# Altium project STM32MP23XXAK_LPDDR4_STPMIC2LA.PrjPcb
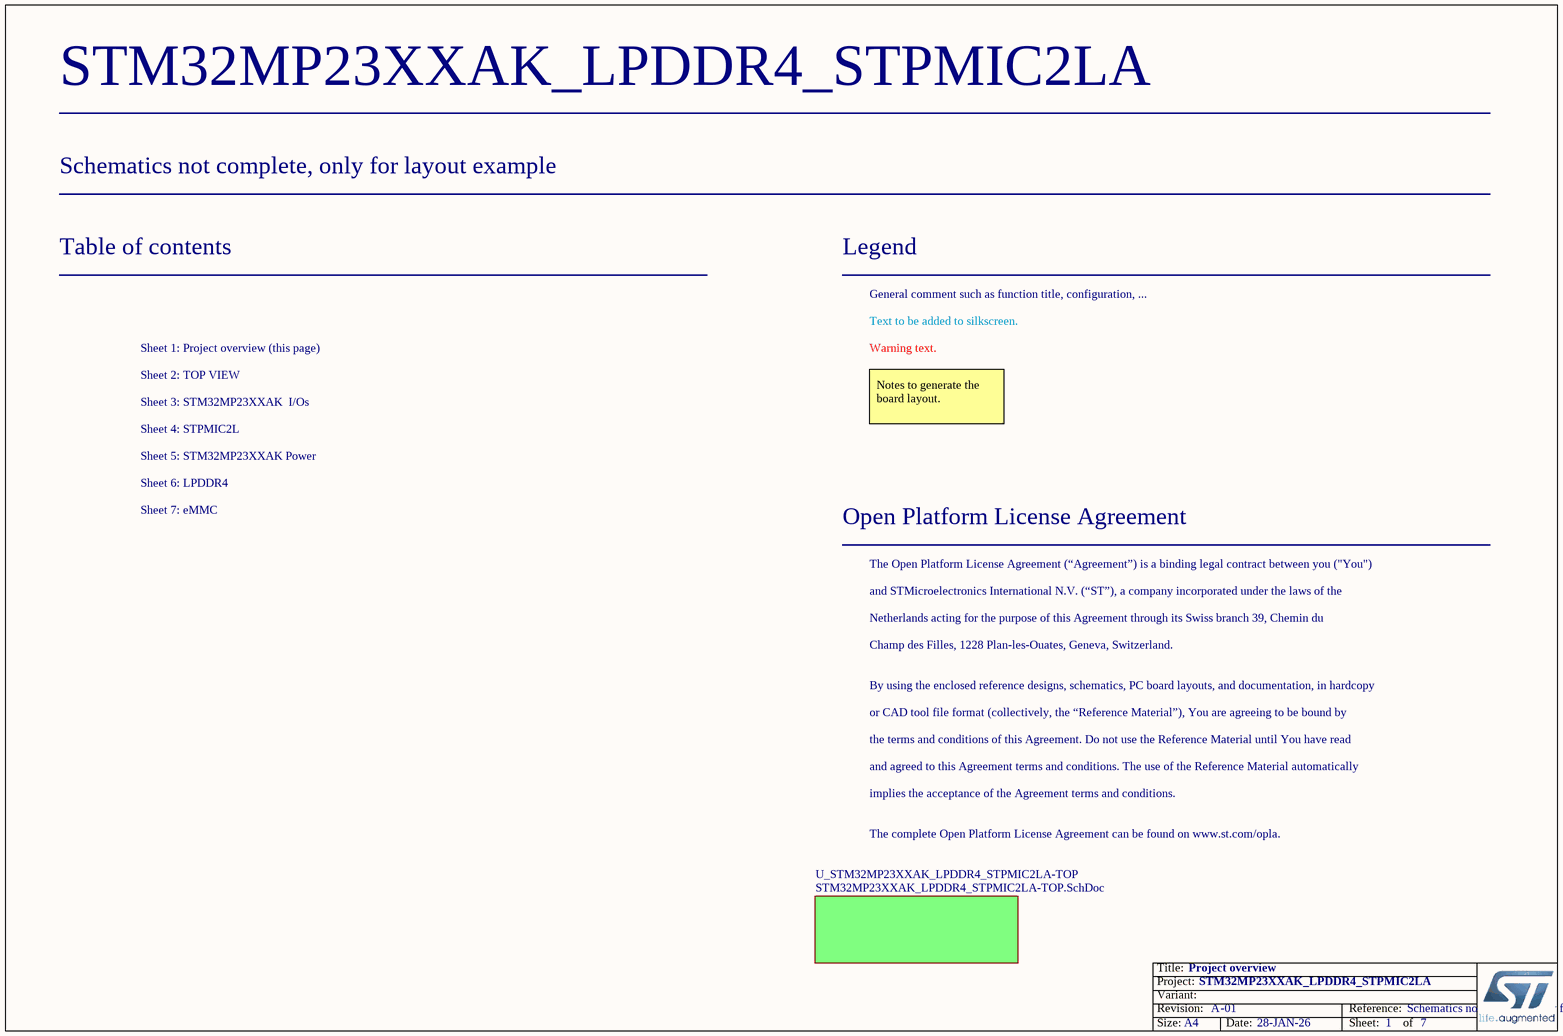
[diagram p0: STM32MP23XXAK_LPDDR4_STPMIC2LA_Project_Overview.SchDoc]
Board_Reference: Schematics not complete, only for layout example; Board_PCB_Revision: A; Board_Name: STM32MP23XXAK_LPDDR4_STPMIC2LA; Board_Document_Date: 28-JAN-26; Board_Assembly_Revision: 01
7 sheets, 156 parts. Net scope: flat (ports and power ports of the same name join across sheets).
Board file: STM32MP23XXAK_LPDDR4_STPMIC2L.PcbDoc
Sheets:
  STM32MP23XXAK_LPDDR4_STPMIC2LA_Project_Overview.SchDoc
    U_STM32MP23XXAK_LPDDR4_STPMIC2LA-TOP = STM32MP23XXAK_LPDDR4_STPMIC2LA-TOP.SchDoc
      U_STM32MP23XXAK I_Os = STM32MP23XXAK I_Os.SchDoc
      U_PMIC = STPMIC2L.SchDoc
      U_STM32MP23XXAK Power = STM32MP23XXAK Power.SchDoc
      U_LPDDR4 = LPDDR4.SchDoc
      U_eMMC = eMMC.SchDoc

## Sheet STM32MP23XXAK_LPDDR4_STPMIC2LA_Project_Overview.SchDoc: Project overview
size A4; Date: Not used; ApprovedBy: Not used; CheckedBy: Not used; Author: Not used; CompanyName: STMicroelectronics; DrawnBy: Not used; Engineer: Not used; Organization: Not used; Address1: Not used; Address2: Not used; Address3: Not used; Address4: Not used; DocumentNumber: Not used; Revision: Not used; SheetNumber: 1; SheetTotal: 7

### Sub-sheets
U_STM32MP23XXAK_LPDDR4_STPMIC2LA-TOP = STM32MP23XXAK_LPDDR4_STPMIC2LA-TOP.SchDoc: no entries

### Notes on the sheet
- Table of contents
- Legend
- General comment such as function title, configuration, ...
- Sheet 1: Project overview (this page)
- Sheet 2: TOP VIEW
- Text to be added to silkscreen.
- Warning text.
- Sheet 3: STM32MP23XXAK  I/Os
- Sheet 4: STPMIC2L
- Notes to generate the board layout.
- Sheet 5: STM32MP23XXAK Power
- Sheet 7: eMMC
- Sheet 6: LPDDR4
- Open Platform License Agreement
- The Open Platform License Agreement (“Agreement”) is a binding legal contract between you ("You")
- and STMicroelectronics International N.V. (“ST”), a company incorporated under the laws of the
- Netherlands acting for the purpose of this Agreement through its Swiss branch 39, Chemin du
- Champ des Filles, 1228 Plan-les-Ouates, Geneva, Switzerland.
- By using the enclosed reference designs, schematics, PC board layouts, and documentation, in hardcopy
- or CAD tool file format (collectively, the “Reference Material”), You are agreeing to be bound by
- the terms and conditions of this Agreement. Do not use the Reference Material until You have read
- and agreed to this Agreement terms and conditions. The use of the Reference Material automatically
- implies the acceptance of the Agreement terms and conditions.
- The complete Open Platform License Agreement can be found on www.st.com/opla.

## Sheet STM32MP23XXAK_LPDDR4_STPMIC2LA-TOP.SchDoc: STM32MP25XXAK-TOP
size A3; Date: Not used; ApprovedBy: Not used; CheckedBy: Not used; Author: Not used; CompanyName: STMicroelectronics; DrawnBy: Not used; Engineer: Not used; Organization: Not used; Address1: Not used; Address2: Not used; Address3: Not used; Address4: Not used; DocumentNumber: Not used; Revision: Not used; SheetNumber: 2; SheetTotal: 7
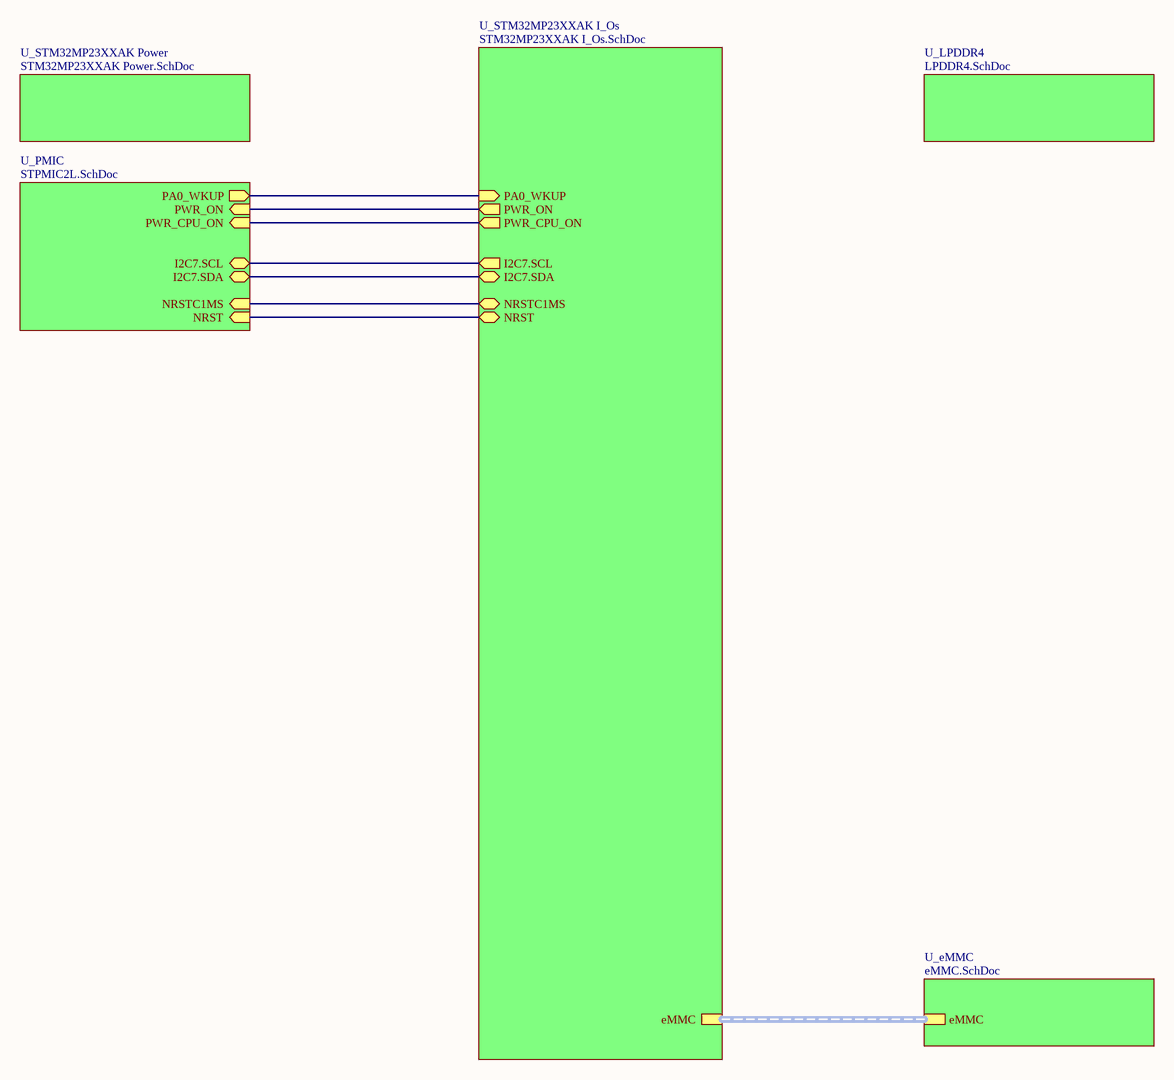
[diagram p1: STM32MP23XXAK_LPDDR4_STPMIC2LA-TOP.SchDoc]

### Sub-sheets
U_eMMC = eMMC.SchDoc: eMMC (harness eMMC)
U_LPDDR4 = LPDDR4.SchDoc: no entries
U_PMIC = STPMIC2L.SchDoc: NRST (in), I2C7.SCL (bidir), PWR_ON (in), PWR_CPU_ON (in), NRSTC1MS (in), I2C7.SDA (bidir), PA0_WKUP (out)
U_STM32MP23XXAK I_Os = STM32MP23XXAK I_Os.SchDoc: NRST (bidir), PWR_ON (out), NRSTC1MS (bidir), I2C7.SDA (bidir), I2C7.SCL (out), PWR_CPU_ON (out), PA0_WKUP (in), eMMC (harness eMMC)
U_STM32MP23XXAK Power = STM32MP23XXAK Power.SchDoc: no entries

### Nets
(unnamed): sheet U_STM32MP23XXAK I_Os/NRST, sheet U_PMIC/NRST
(unnamed): sheet U_STM32MP23XXAK I_Os/PWR_ON, sheet U_PMIC/PWR_ON  [a separate net that carries the same name]
(unnamed): sheet U_STM32MP23XXAK I_Os/NRSTC1MS, sheet U_PMIC/NRSTC1MS  [a separate net that carries the same name]
(unnamed): sheet U_STM32MP23XXAK I_Os/I2C7.SDA, sheet U_PMIC/I2C7.SDA  [a separate net that carries the same name]
(unnamed): sheet U_STM32MP23XXAK I_Os/I2C7.SCL, sheet U_PMIC/I2C7.SCL  [a separate net that carries the same name]
(unnamed): sheet U_STM32MP23XXAK I_Os/PWR_CPU_ON, sheet U_PMIC/PWR_CPU_ON  [a separate net that carries the same name]
(unnamed): sheet U_STM32MP23XXAK I_Os/PA0_WKUP, sheet U_PMIC/PA0_WKUP  [a separate net that carries the same name]

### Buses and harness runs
harness sheet U_eMMC/eMMC = sheet U_STM32MP23XXAK I_Os/eMMC

## Sheet STM32MP23XXAK I_Os.SchDoc: STM32MP25XXAK  I/Os
size A3; Date: Not used; ApprovedBy: Not used; CheckedBy: Not used; Author: Not used; CompanyName: STMicroelectronics; DrawnBy: Not used; Engineer: Not used; Organization: Not used; Address1: Not used; Address2: Not used; Address3: Not used; Address4: Not used; DocumentNumber: Not used; Revision: Not used; SheetNumber: 3; SheetTotal: 7
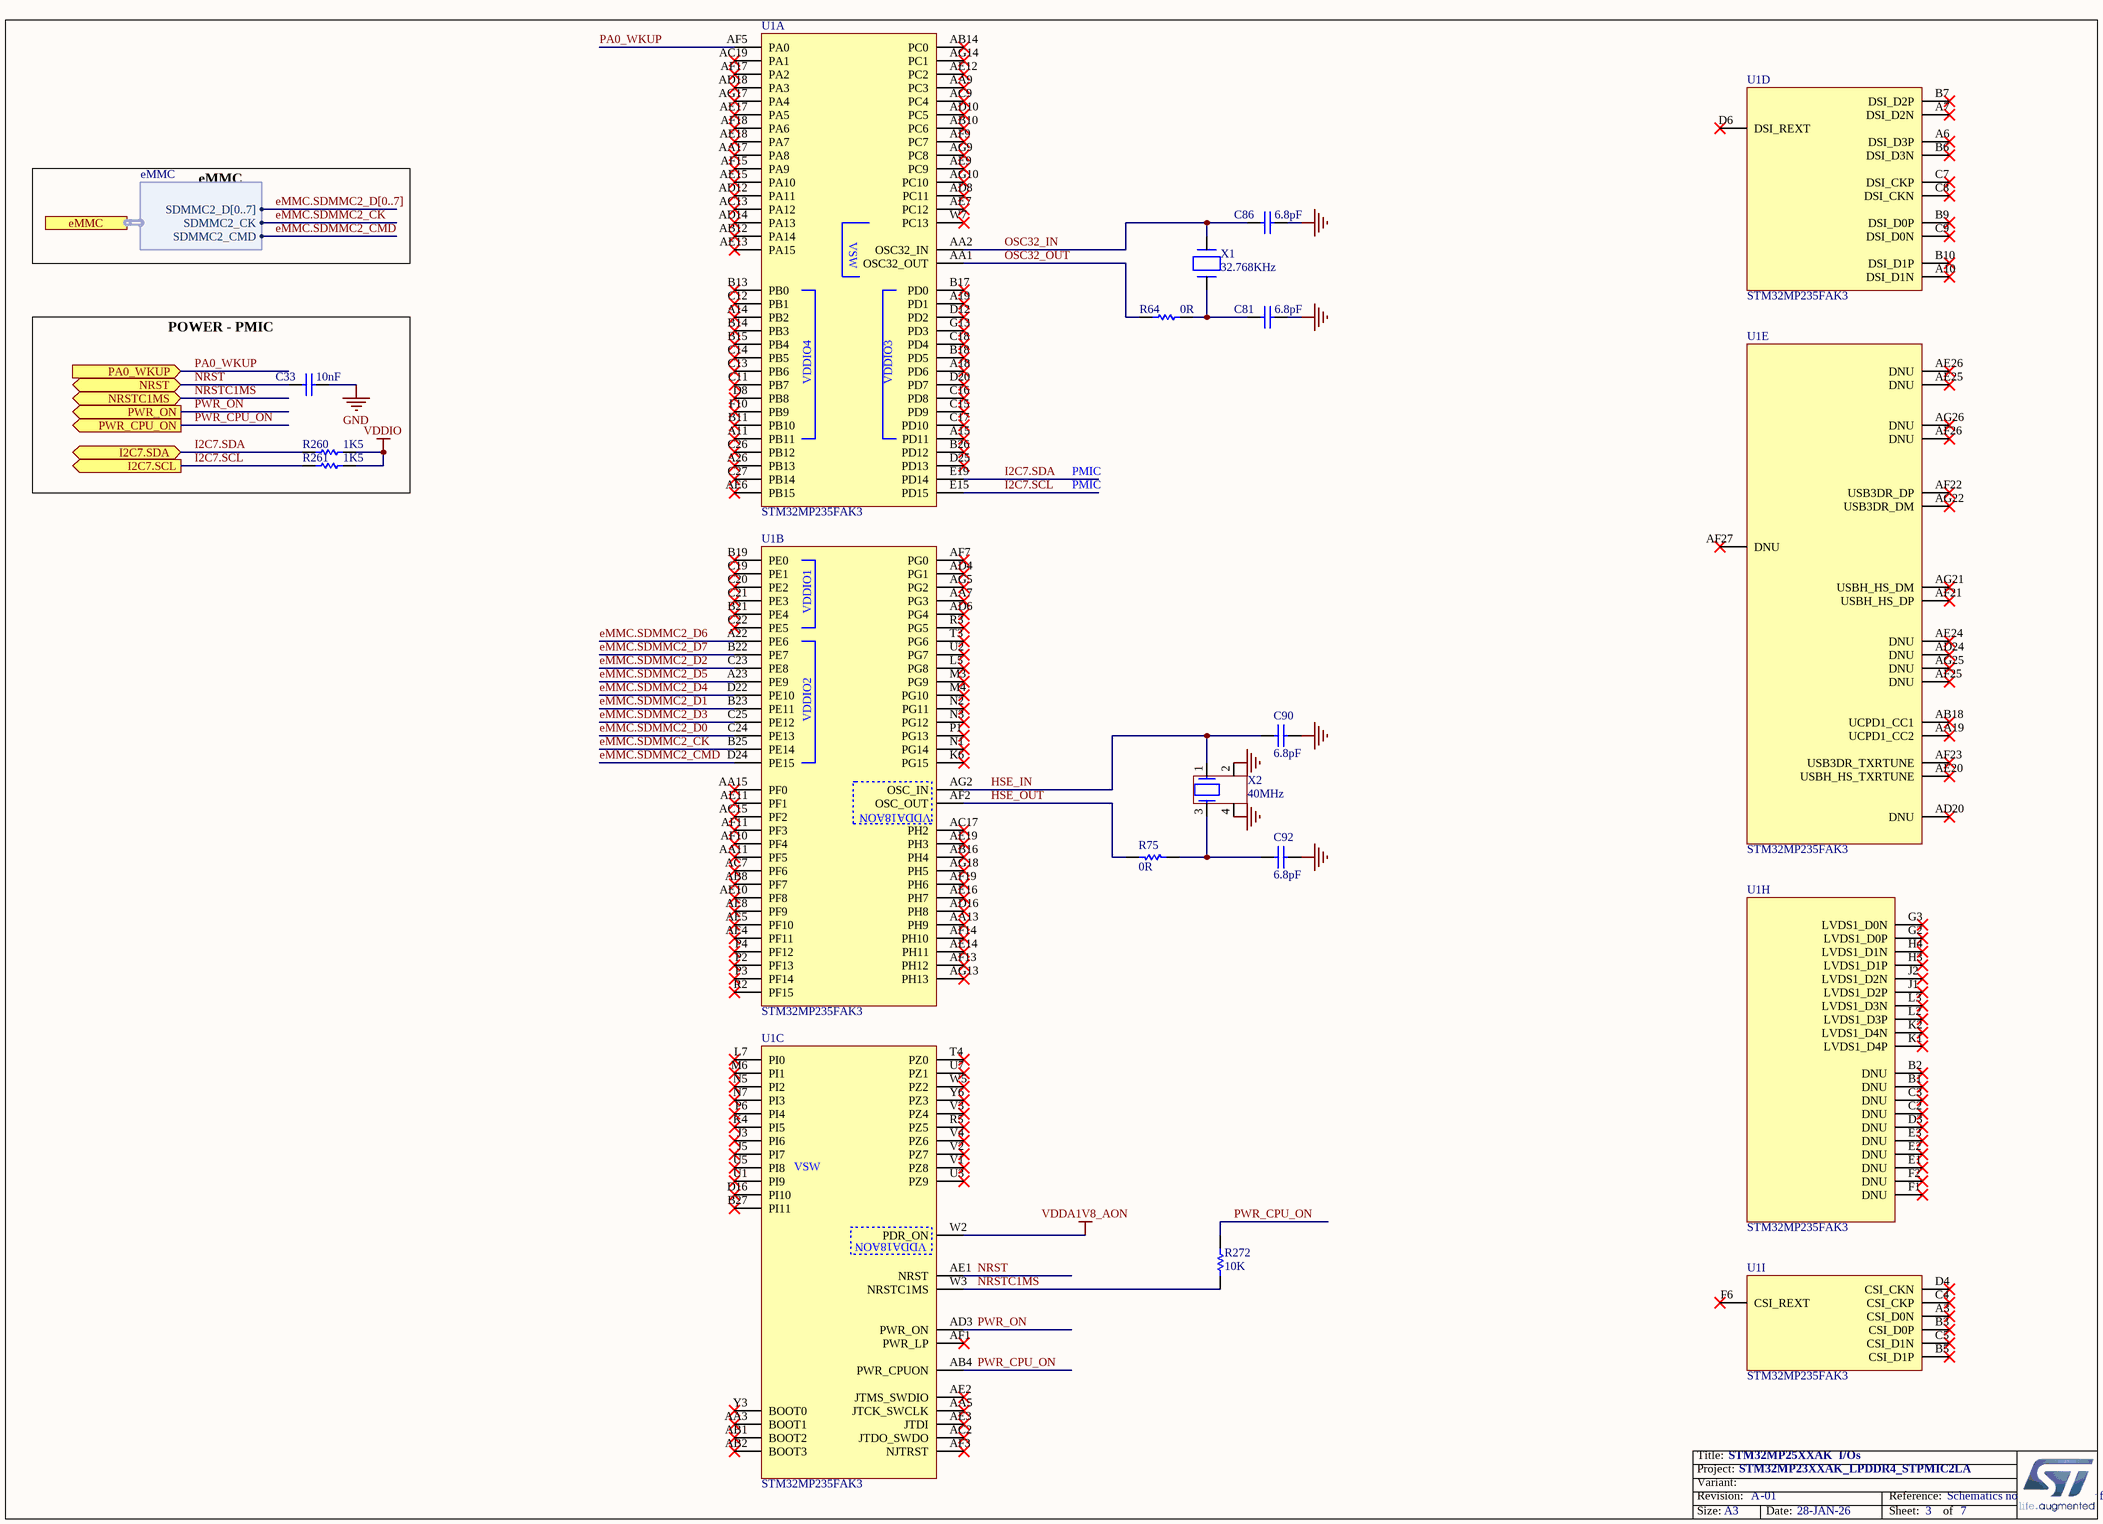
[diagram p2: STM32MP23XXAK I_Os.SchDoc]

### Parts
C33  value 10nF  [C0402]  (hidden comment: Capacitor)
C81  value 6.8pF  [C0402]  (hidden comment: Capacitor)
C86  value 6.8pF  [C0402]  (hidden comment: Capacitor)
C90  value 6.8pF  [C0402]  (hidden comment: Capacitor)
C92  value 6.8pF  [C0402]  (hidden comment: Capacitor)
R64  value 0R  [R0402]  (hidden comment: Resistor)
R75  value 0R  [R0402]  (hidden comment: Resistor)
R260  value 1K5  [R0402]  (hidden comment: Resistor)
R261  value 1K5  [R0402]  (hidden comment: Resistor)
R272  value 10K  [R0402]  (hidden comment: Resistor)
U1  value STM32MP235FAK3  [ICC_VFBGA424_14X14_P050_H1P0_CODE-B0MP]  (hidden comment: IC_STM32MP235FAK3)  (parts A,B,C,D,E,H,I of 9)
X1  value 32.768KHz  [CRY_NX2012SA_2P]  (hidden comment: XTAL_2_PINS)
X2  value 40MHz  [CRY_NX1612SA_4P]  (hidden comment: XTAL_4_PINS)

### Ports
eMMC (harness eMMC), I2C7.SCL (out), I2C7.SDA (bidir), NRST (bidir), NRSTC1MS (bidir), PA0_WKUP (in), PWR_CPU_ON (out), PWR_ON (out)

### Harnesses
eMMC: SDMMC2_CK, SDMMC2_CMD, SDMMC2_D[0..7]

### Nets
GND: C33.1 C81.2 C86.2 C90.1 C92.2 X2.2 X2.4
VDDA1V8_AON: U1.W2(PDR_ON)
VDDIO: R260.2 R261.2
eMMC.SDMMC2_CK: U1.B25(PE14) ; port eMMC.SDMMC2_CK
eMMC.SDMMC2_CMD: U1.D24(PE15) ; port eMMC.SDMMC2_CMD
eMMC.SDMMC2_D0: U1.C24(PE13)
eMMC.SDMMC2_D1: U1.B23(PE11)
eMMC.SDMMC2_D2: U1.C23(PE8)
eMMC.SDMMC2_D3: U1.C25(PE12)
eMMC.SDMMC2_D4: U1.D22(PE10)
eMMC.SDMMC2_D5: U1.A23(PE9)
eMMC.SDMMC2_D6: U1.A22(PE6)
eMMC.SDMMC2_D7: U1.B22(PE7)
HSE_IN: C90.2 U1.AG2(OSC_IN) X2.1
HSE_OUT: R75.2 U1.AF2(OSC_OUT)
I2C7.SCL: R261.1 U1.E15(PD15) ; port I2C7.SCL
I2C7.SDA: R260.1 U1.E19(PD14) ; port I2C7.SDA
NRST: C33.2 U1.AE1(NRST) ; port NRST
NRSTC1MS: R272.1 U1.W3(NRSTC1MS) ; port NRSTC1MS
OSC32_IN: C86.1 U1.AA2(OSC32_IN) X1.2(X2)
OSC32_OUT: R64.1 U1.AA1(OSC32_OUT)
PA0_WKUP: U1.AF5(PA0) ; port PA0_WKUP
PWR_CPU_ON: R272.2 U1.AB4(PWR_CPUON) ; port PWR_CPU_ON
PWR_ON: U1.AD3(PWR_ON) ; port PWR_ON
NetC81_1: C81.1 R64.2 X1.1(X1)
NetC92_1: C92.1 R75.1 X2.3

Not connected (* = marked no-connect by the designer): U1 A3(CSI_D0N)* A6(DSI_D3P)* A7(DSI_D2N)* A10(DSI_D1N)* A11(PB11)* A14(PB2)* A15(PD11)* A18(PD6)* A19(PD1)* A26(PB13)* AA3(BOOT1)* AA5(JTCK_SWCLK)* AA7(PG3)* AA9(PC3)* AA11(PF5)* AA13(PH9)* AA15(PF0)* AA17(PA8)* AA19(UCPD1_CC2)* AB1(BOOT2)* AB2(BOOT3)* AB8(PF7)* AB10(PC6)* AB12(PA14)* AB14(PC0)* AB16(PH4)* AB18(UCPD1_CC1)* AC2(JTDO_SWDO)* AC7(PF6)* AC9(PC4)* AC13(PA12)* AC15(PF2)* AC17(PH2)* AC19(PA1)* AD4(PG1)* AD6(PG4)* AD8(PC11)* AD10(PC5)* AD12(PA11)* AD14(PA13)* AD16(PH8)* AD18(PA3)* AD20(DNU)* AD24(DNU)* AE2(JTMS_SWDIO)* AE3(JTDI)* AE4(PF11)* AE5(PF10)* AE6(PB15)* AE7(PC12)* AE8(PF9)* AE9(PC9)* AE10(PF8)* AE11(PF1)* AE12(PC2)* AE13(PA15)* AE14(PH11)* AE15(PA10)* AE16(PH7)* AE17(PA5)* AE18(PA7)* AE19(PH3)* AE20(USBH_HS_TXRTUNE)* AE24(DNU)* AE25(DNU)* AE26(DNU)* AF1(PWR_LP)* AF3(NJTRST)* AF7(PG0)* AF9(PC7)* AF10(PF4)* AF11(PF3)* AF13(PH12)* AF14(PH10)* AF15(PA9)* AF17(PA2)* AF18(PA6)* AF19(PH6)* AF21(USBH_HS_DP)* AF22(USB3DR_DP)* AF23(USB3DR_TXRTUNE)* AF25(DNU)* AF26(DNU)* AF27(DNU)* AG5(PG2)* AG9(PC8)* AG10(PC10)* AG13(PH13)* AG14(PC1)* AG17(PA4)* AG18(PH5)* AG21(USBH_HS_DM)* AG22(USB3DR_DM)* AG25(DNU)* AG26(DNU)* B1(DNU)* B2(DNU)* B3(CSI_D0P)* B5(CSI_D1P)* B6(DSI_D3N)* B7(DSI_D2P)* B9(DSI_D0P)* B10(DSI_D1P)* B11(PB10)* B13(PB0)* B14(PB3)* B15(PB4)* B17(PD0)* B18(PD5)* B19(PE0)* B21(PE4)* B26(PD12)* B27(PI11)* C2(DNU)* C3(DNU)* C4(CSI_CKP)* C5(CSI_D1N)* C7(DSI_CKP)* C8(DSI_CKN)* C9(DSI_D0N)* C11(PB7)* C12(PB1)* C13(PB6)* C14(PB5)* C15(PD9)* C16(PD8)* C17(PD10)* C18(PD4)* C19(PE1)* C20(PE2)* C21(PE3)* C22(PE5)* C26(PB12)* C27(PB14)* D3(DNU)* D4(CSI_CKN)* D6(DSI_REXT)* D8(PB8)* D12(PD2)* D16(PI10)* D20(PD7)* D25(PD13)* E1(DNU)* E2(DNU)* E3(DNU)* F1(DNU)* F2(DNU)* F6(CSI_REXT)* F10(PB9)* G2(LVDS1_D0P)* G3(LVDS1_D0N)* G13(PD3)* H3(LVDS1_D1P)* H4(LVDS1_D1N)* J1(LVDS1_D2P)* J2(LVDS1_D2N)* J3(PI6)* J5(PI7)* K1(LVDS1_D4P)* K2(LVDS1_D4N)* K4(PI5)* K6(PG15)* L2(LVDS1_D3P)* L3(LVDS1_D3N)* L5(PG8)* L7(PI0)* M3(PG9)* M4(PG10)* M6(PI1)* N1(PG14)* N2(PG11)* N3(PG12)* N5(PI2)* N7(PI3)* P1(PG13)* P2(PF13)* P3(PF14)* P4(PF12)* P6(PI4)* R2(PF15)* R3(PG5)* R5(PZ5)* T3(PG6)* T4(PZ0)* U1(PI9)* U2(PG7)* U3(PZ9)* U5(PI8)* U7(PZ1)* V1(PZ8)* V2(PZ7)* V3(PZ4)* V4(PZ6)* W5(PZ2)* W7(PC13)* Y3(BOOT0)* Y6(PZ3)*

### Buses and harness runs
bus eMMC.SDMMC2_D[0..7]

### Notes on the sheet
- eMMC
- POWER - PMIC
- PMIC

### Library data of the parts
C33 = MCD-00011: Capacitor, MLCC, 10nF, 16V, X7R, +/-10%, 0402, T=0.5mm; Manufacturer_Part_Number: CC0402KRX7R7BB103; Manufacturer: YAGEO; Part_Preference: Recommended; Order_Code_RS: 3019275; Component_Country_Of_Origin: China; ShowFields: YES; ID: 2469
C81 C86 C90 C92 = MCD-00674: Capacitor, MLCC, 6.8pF, 50V, C0G/NP0, +/-0.25pF, 0402, T=0.5mm; Manufacturer_Part_Number: CC0402CRNPO9BN6R8; Manufacturer: YAGEO; Part_Preference: Recommended; Component_Country_Of_Origin: China; ID: 3068; ShowFields: YES
R64 R75 = MCD-00052: Resistor, 0R, 0402, +/-5%, 1/16W; Manufacturer_Part_Number: RC0402JR-070RL; Manufacturer: YAGEO; Part_Preference: Recommended; Order_Code_RS: 9232516RL; Component_Country_Of_Origin: China; ID: 2540; ShowFields: YES
R260 R261 = MCD-00068: Resistor, 1K5, 0402, +/-1%, 1/16W; Part_Preference: Recommended; Manufacturer: YAGEO; Manufacturer_Part_Number: RC0402FR-071K5L; Order_Code_RS: 9239251; Component_Country_Of_Origin: China; ID: 2524; ShowFields: YES
R272 = MCD-00053: Resistor, 10K, 0402, +/-1%, 1/16W; BMS_Part_Number: 9131590; Part_Preference: Recommended; Manufacturer: YAGEO; Manufacturer_Part_Number: RC0402FR-0710KL; Order_Code_RS: 9239359; Component_Country_Of_Origin: China; ID: 2539; ShowFields: YES
U1 = MCD-05079: MPU, dual core ARM cortex-A35 64-bit + M33 32-bit, 776KB SRAM, With Crypto; Part_Type: IC; Part_Preference: Recommended; Manufacturer: STMICROELECTRONICS; ShowFields: YES; ID: 7195
X1 = MCD-01479: Crystal, 32.768kHz, 6pF, +/-20ppm, 80K, 2.05x1.2mm; BMS_Part_Number: 9157049; Part_Type: Crystal_Osc; Part_Preference: Recommended; Manufacturer: NDK; Manufacturer_Part_Number: NX2012SA-32.768KHz-EXS00A-MU00527; Component_Country_Of_Origin: Japan; ShowFields: YES; ID: 3579
X2 = MCD-02344: Crystal, 40MHz, 6pF, +/-20ppm, 80R, 1.6x1.2mm; Part_Type: Crystal_Osc; Part_Preference: Recommended; Manufacturer: NDK; Manufacturer_Part_Number: NX1612SA-40MHz-EXS00A-CS13836; Component_Country_Of_Origin: Japan; ShowFields: YES; ID: 4450

## Sheet STPMIC2L.SchDoc: Power PMIC
size A3; Date: Not used; ApprovedBy: Not used; CheckedBy: Not used; Author: Not used; CompanyName: STMicroelectronics; DrawnBy: Not used; Engineer: Not used; Organization: Not used; Address1: Not used; Address2: Not used; Address3: Not used; Address4: Not used; DocumentNumber: Not used; Revision: Not used; SheetNumber: 4; SheetTotal: 19
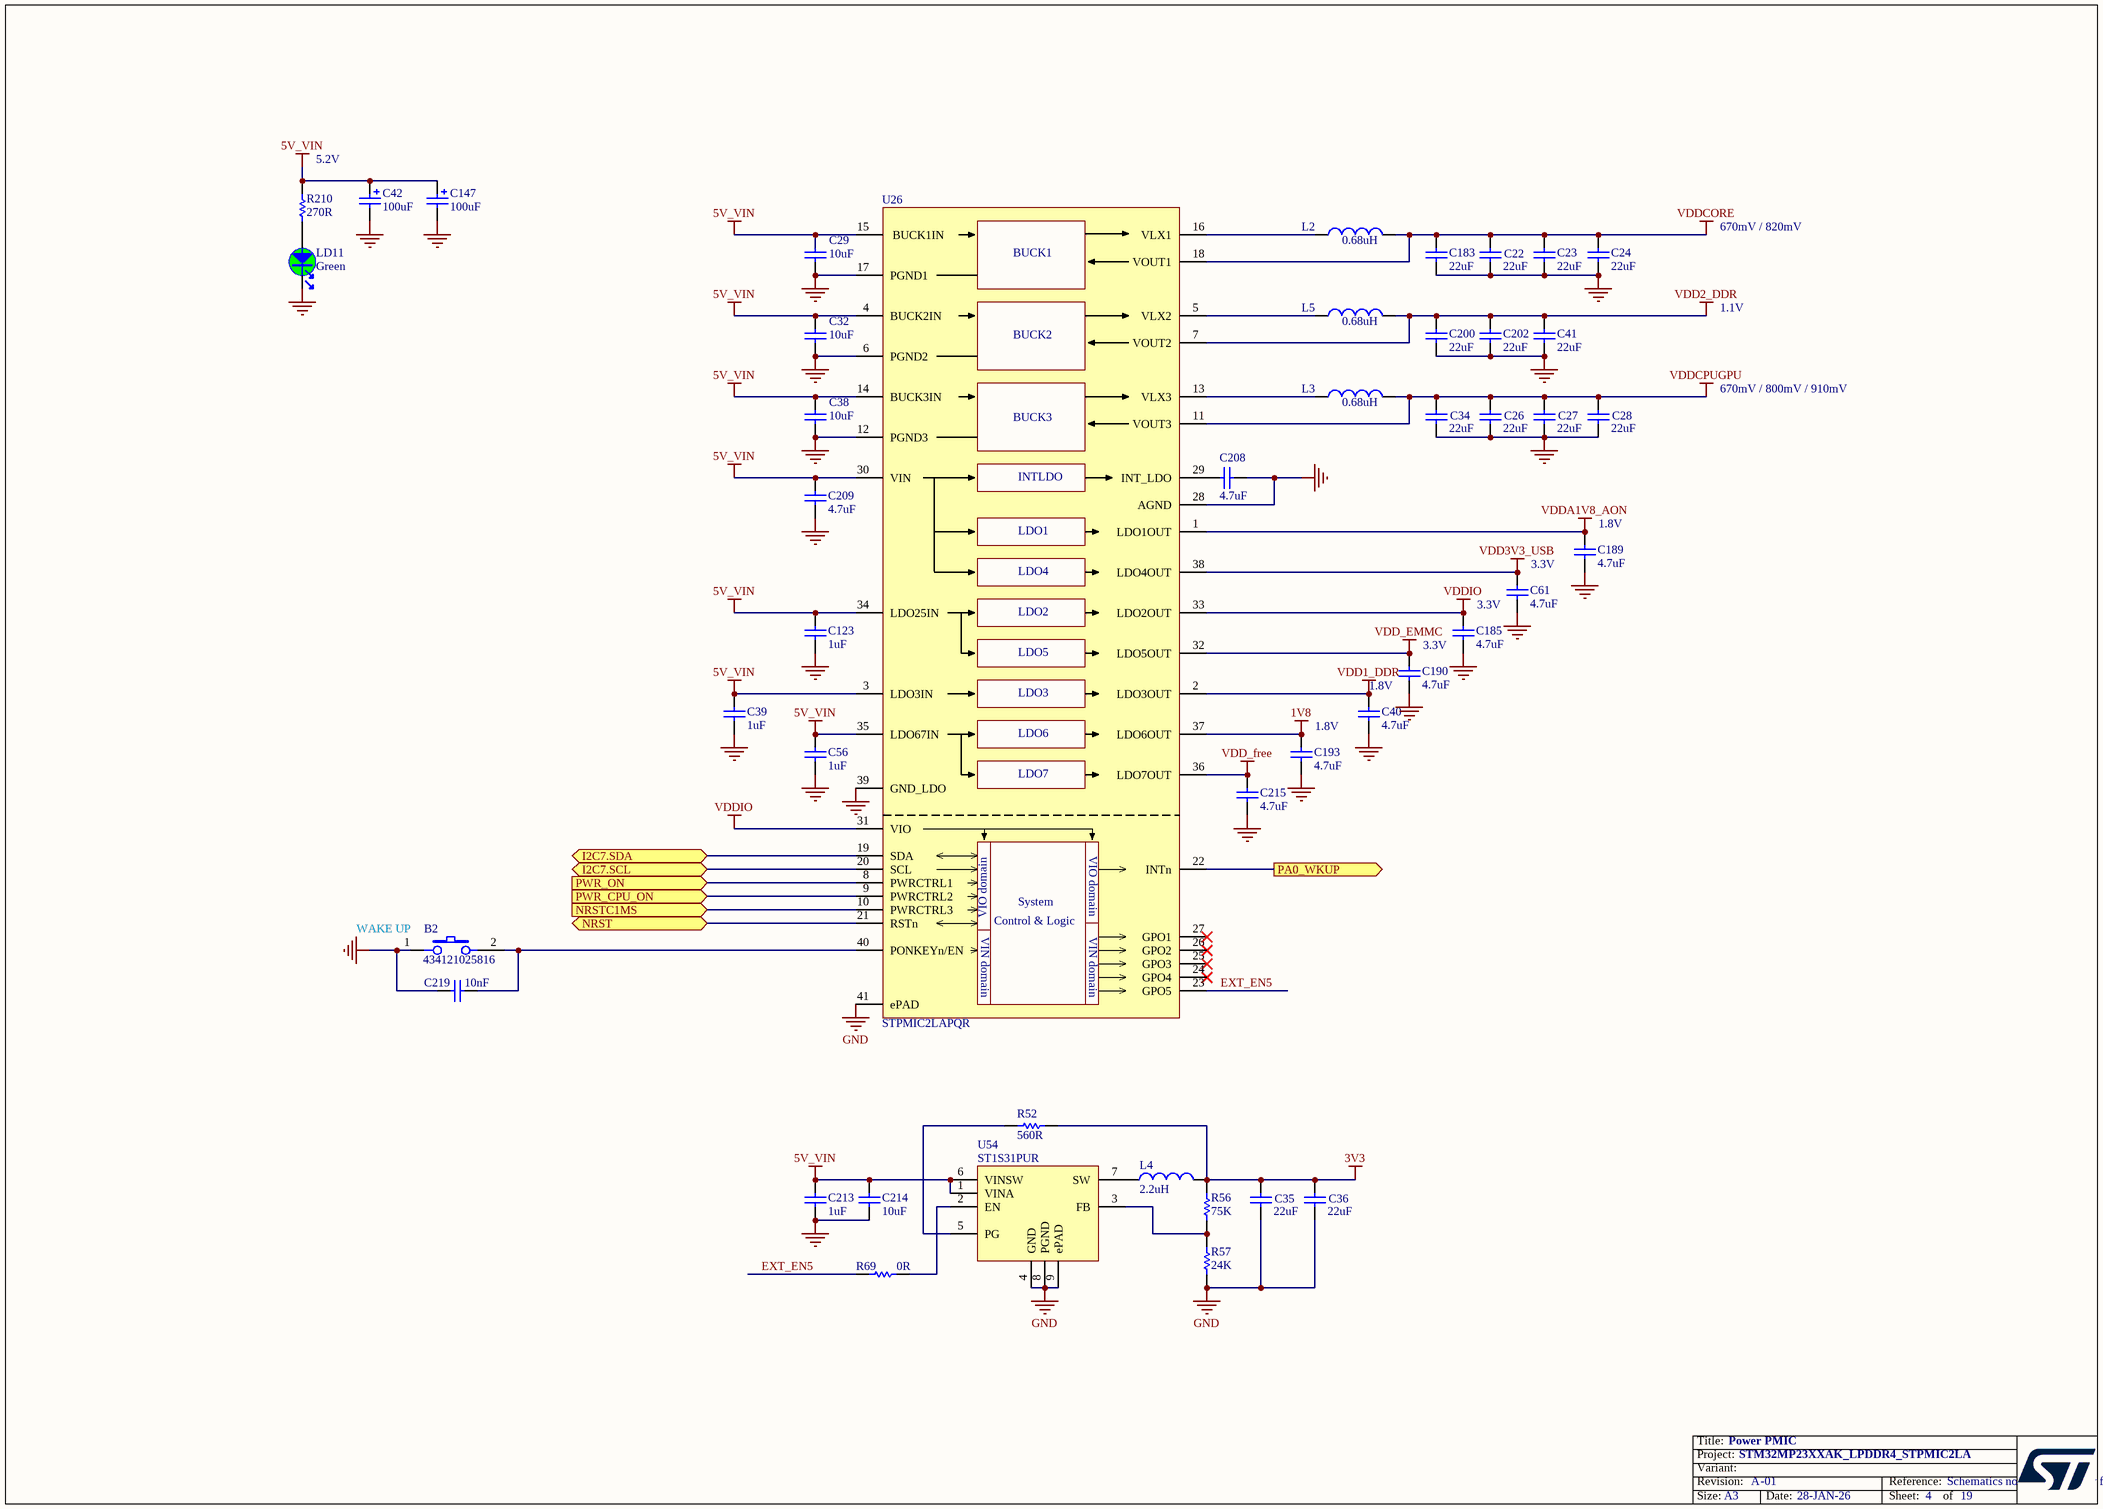
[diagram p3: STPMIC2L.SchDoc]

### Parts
B2  value 434121025816  [SWI_WE_434121025816]  (hidden comment: SW_PUSH_SMD_2P)
C22  value 22uF  [C0603]  (hidden comment: Capacitor)
C23  value 22uF  [C0603]  (hidden comment: Capacitor)
C24  value 22uF  [C0603]  (hidden comment: Capacitor)
C26  value 22uF  [C0603]  (hidden comment: Capacitor)
C27  value 22uF  [C0603]  (hidden comment: Capacitor)
C28  value 22uF  [C0603]  (hidden comment: Capacitor)
C29  value 10uF  [C0603]  (hidden comment: Capacitor)
C32  value 10uF  [C0603]  (hidden comment: Capacitor)
C34  value 22uF  [C0603]  (hidden comment: Capacitor)
C35  value 22uF  [C0603]  (hidden comment: Capacitor)
C36  value 22uF  [C0603]  (hidden comment: Capacitor)
C38  value 10uF  [C0603]  (hidden comment: Capacitor)
C39  value 1uF  [C0402]  (hidden comment: Capacitor)
C40  value 4.7uF  [C0402]  (hidden comment: Capacitor)
C41  value 22uF  [C0603]  (hidden comment: Capacitor)
C42  value 100uF  [CPOL_TCJ-B_1210_H210]  (hidden comment: CAP_POL)
C56  value 1uF  [C0402]  (hidden comment: Capacitor)
C61  value 4.7uF  [C0402]  (hidden comment: Capacitor)
C123  value 1uF  [C0402]  (hidden comment: Capacitor)
C147  value 100uF  [CPOL_TCJ-B_1210_H210]  (hidden comment: CAP_POL)
C183  value 22uF  [C0603]  (hidden comment: Capacitor)
C185  value 4.7uF  [C0402]  (hidden comment: Capacitor)
C189  value 4.7uF  [C0402]  (hidden comment: Capacitor)
C190  value 4.7uF  [C0402]  (hidden comment: Capacitor)
C193  value 4.7uF  [C0402]  (hidden comment: Capacitor)
C200  value 22uF  [C0603]  (hidden comment: Capacitor)
C202  value 22uF  [C0603]  (hidden comment: Capacitor)
C208  value 4.7uF  [C0402]  (hidden comment: Capacitor)
C209  value 4.7uF  [C0402]  (hidden comment: Capacitor)
C213  value 1uF  [C0402]  (hidden comment: Capacitor)
C214  value 10uF  [C0603]  (hidden comment: Capacitor)
C215  value 4.7uF  [C0402]  (hidden comment: Capacitor)
C219  value 10nF  [C0402]  (hidden comment: Capacitor)
L2  value 0.68uH  [IND_2016_MURATA_DFE2016]  (hidden comment: Inductor)
L3  value 0.68uH  [IND_2016_MURATA_DFE2016]  (hidden comment: Inductor)
L4  value 2.2uH  [IND_2520_TOKO_DFE252012P]  (hidden comment: Inductor)
L5  value 0.68uH  [IND_2016_MURATA_DFE2016]  (hidden comment: Inductor)
LD11  value Green  [LED_0603_OSRAM_LG-Q396-PS-35_GREEN_1A2K_H0P4]  (hidden comment: LED_green)
R52  value 560R  [R0402]  (hidden comment: Resistor)
R56  value 75K  [R0402]  (hidden comment: Resistor)
R57  value 24K  [R0402]  (hidden comment: Resistor)
R69  value 0R  [R0402]  (hidden comment: Resistor)
R210  value 270R  [R0402]  (hidden comment: Resistor)
U26  value STPMIC2LAPQR  [ICC_VFQFPN40-EPAD_5X5_P040]  (hidden comment: STPMIC2L)
U54  ST1S31PUR  [ICC_VFDFPN8-EPAD_3X3_P065]

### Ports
I2C7.SCL (bidir), I2C7.SDA (bidir), NRST (bidir), NRSTC1MS (in), PA0_WKUP (out), PWR_CPU_ON (in), PWR_ON (in)

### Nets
1V8: C193.1 U26.37(LDO6OUT)
3V3: C35.2 C36.2 L4.2 R52.2 R56.2
5V_VIN: C29.2 C32.2 C38.2 C39.2 C42.1 C56.2 C123.2 C147.1 C209.2 C213.2 C214.2 R210.1 U26.3(LDO3IN) U26.4(BUCK2IN) U26.14(BUCK3IN) U26.15(BUCK1IN) U26.30(VIN) U26.34(LDO25IN) U26.35(LDO67IN) U54.1(VINA) U54.6(VINSW)
GND: B2.1 C22.1 C23.1 C24.1 C26.1 C27.1 C28.1 C29.1 C32.1 C34.1 C35.1 C36.1 C38.1 C39.1 C40.2 C41.1 C42.2 C56.1 C61.2 C123.1 C147.2 C183.1 C185.2 C189.2 C190.2 C193.2 C200.1 C202.1 C208.1 C209.1 C213.1 C214.1 C215.1 C219.1 LD11.2 R57.1 U26.6(PGND2) U26.12(PGND3) U26.17(PGND1) U26.28(AGND) U26.39(GND_LDO) U26.41(ePAD) U54.4(GND) U54.8(PGND) U54.9(ePAD)
VDD1_DDR: C40.1 U26.2(LDO3OUT)
VDD2_DDR: C41.2 C200.2 C202.2 L5.2 U26.7(VOUT2)
VDD3V3_USB: C61.1 U26.38(LDO4OUT)
VDD_EMMC: C190.1 U26.32(LDO5OUT)
VDD_free: C215.2 U26.36(LDO7OUT)
VDDA1V8_AON: C189.1 U26.1(LDO1OUT)
VDDCORE: C22.2 C23.2 C24.2 C183.2 L2.2 U26.18(VOUT1)
VDDCPUGPU: C26.2 C27.2 C28.2 C34.2 L3.2 U26.11(VOUT3)
VDDIO: C185.1 U26.31(VIO) U26.33(LDO2OUT)
EXT_EN5: R69.1 U26.23(GPO5)
I2C7.SCL: U26.20(SCL) ; port I2C7.SCL
I2C7.SDA: U26.19(SDA) ; port I2C7.SDA
NRST: U26.21(RSTn) ; port NRST
NRSTC1MS: U26.10(PWRCTRL3) ; port NRSTC1MS
PA0_WKUP: U26.22(INTn) ; port PA0_WKUP
PWR_CPU_ON: U26.9(PWRCTRL2) ; port PWR_CPU_ON
PWR_ON: U26.8(PWRCTRL1) ; port PWR_ON
NetB2_2: B2.2 C219.2 U26.40(PONKEYn/EN)
NetC208_2: C208.2 U26.29(INT_LDO)
NetL2_1: L2.1 U26.16(VLX1)
NetL3_1: L3.1 U26.13(VLX3)
NetL4_1: L4.1 U54.7(SW)
NetL5_1: L5.1 U26.5(VLX2)
NetLD11_1: LD11.1 R210.2
NetR52_1: R52.1 U54.5(PG)
NetR56_1: R56.1 R57.2 U54.3(FB)
NetR69_2: R69.2 U54.2(EN)

Not connected (* = marked no-connect by the designer): U26 24(GPO4)* 25(GPO3)* 26(GPO2)* 27(GPO1)*

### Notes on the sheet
- 5.2V
- 670mV / 820mV
- 1.1V
- 670mV / 800mV / 910mV
- 3.3V
- (near C189) 1.8V
- 1.8V
- (near B2) WAKE UP

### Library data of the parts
B2 = MCD-03492: Switch tactile, SPST-NO, 12V, 50mA, 3x2.6mm; Part_Type: Misc; Part_Preference: Recommended; Manufacturer: WURTH ELEKTRONIK; Order_Code_RS: 1867991; Component_Country_Of_Origin: China; ShowFields: YES; ID: 5608
C22 C26-C28 C34-C36 C41 C202 = MCD-00100: Capacitor, MLCC, 22uF, 6V3, X5R, +/-20%, 0603, T=0.8mm; Manufacturer_Part_Number: GRM188R60J226MEA0; Manufacturer: MURATA; Part_Preference: Recommended; Partial_Alternate_Internal_Part_Number: MCD-04184; Component_Country_Of_Origin: Japan°°; ID: 2766; ShowFields: YES
C23 C24 C183 C200 = MCD-00100: Capacitor, MLCC, 22uF, 6V3, X5R, +/-20%, 0603, T=0.8mm; Part_Preference: Recommended; Manufacturer: MURATA; Manufacturer_Part_Number: GRM188R60J226MEA0; Partial_Alternate_Internal_Part_Number: MCD-04184; Component_Country_Of_Origin: Japan°°; ID: 2766; ShowFields: YES
C29 C32 C38 = MCD-00099: Capacitor, MLCC, 10uF, 10V, X5R, +/-10%, 0603, T=0.8mm; Manufacturer_Part_Number: GRM188R61A106KE69; Manufacturer: MURATA; Part_Preference: Recommended; Partial_Alternate_Internal_Part_Number: MCD-03152; Order_Code_RS: 2494233; Component_Country_Of_Origin: Japan°°; ID: 2770; ShowFields: YES
C39 C56 C123 C213 = MCD-00095: Capacitor, MLCC, 1uF, 25V, X5R, 10%, 0402, T=0.5mm; Part_Preference: Recommended; Manufacturer: MURATA; Manufacturer_Part_Number: GRM155R61E105KA12; Partial_Alternate_Internal_Part_Number: MCD-04188; Order_Code_RS: 2218855; Component_Country_Of_Origin: Japan°°; ShowFields: YES; ID: 2772
C40 C61 C185 C189 C190 C193 C208 C209 C215 = MCD-01356: Capacitor, MLCC, 4.7uF, 6V3, X5R, 20%, 0402, T=0.5mm; Manufacturer_Part_Number: GRM155R60J475ME47; Manufacturer: MURATA; Part_Preference: Recommended; Partial_Alternate_Internal_Part_Number: MCD-04455; Order_Code_RS: 814-5230; Component_Country_Of_Origin: Japan°°; ShowFields: YES; ID: 3456
C42 C147 = MCD-01796: Capacitor, Tantalum, 100uF, 6V3, 40mR, +/-20%,  Type_B (3528 metric), T=1.9mm; Part_Preference: Recommended; Manufacturer: KYOCERA AVX; Manufacturer_Part_Number: TCJB107M006R0040E; Partial_Alternate_Internal_Part_Number: MCD-04209; Component_Country_Of_Origin: Czech Republic; ShowFields: YES; ID: 3896
C214 = MCD-00099: Capacitor, MLCC, 10uF, 10V, X5R, +/-10%, 0603, T=0.8mm; Part_Preference: Recommended; Manufacturer: MURATA; Manufacturer_Part_Number: GRM188R61A106KE69; Partial_Alternate_Internal_Part_Number: MCD-03152; Order_Code_RS: 2494233; Component_Country_Of_Origin: Japan°°; ShowFields: YES; ID: 2770
C219 = MCD-02198: Capacitor, MLCC, 10nF, 50V, X7R, +/-10%, 0402, T=0.5mm; Manufacturer_Part_Number: CC0402KRX7R9BB103; Manufacturer: YAGEO; Part_Preference: Recommended; Order_Code_RS: 6169644; Component_Country_Of_Origin: China; ShowFields: YES; ID: 4298
L2 L3 L5 = MCD-03141: Inductor, 0.68uH, +/-20%, Itemp= 3100mA, Isat= 4300mA, 0R043, 0806, T=1mm; Part_Preference: Recommended; Manufacturer: MURATA; Manufacturer_Part_Number: DFE201610E-R68M=P2; ShowFields: YES; ID: 5257; Component_Country_Of_Origin: Vietnam
L4 = MCD-00161: Inductor, 2.2uH, +/-20%, 2,2A, 84mR, 1008, T=1.2mm; Part_Preference: Recommended; Manufacturer: TOKO; Manufacturer_Part_Number: DFE252012P-2R2M=P2; Order_Code_RS: 167-0606; Component_Country_Of_Origin: Japan°°; ShowFields: YES; ID: 2711
LD11 = MCD-00588: LED, Green, 2V, 20mA, 0603; Part_Type: Display; Manufacturer_Part_Number: LG Q396-PS-35-0-20-R18; Manufacturer: AMS OSRAM; Part_Preference: Forbidden; Partial_Alternate_Internal_Part_Number: MCD-02400, MCD-02901, MCD-03155, MCD-03981, MCD-04229; Component_Country_Of_Origin: Unknown; ID: 3155; ShowFields: YES
R52 = MCD-00489: Resistor, 560R, 0402, +/-1%, 1/16W; Part_Preference: Recommended; Manufacturer: YAGEO; Manufacturer_Part_Number: RC0402FR-07560RL; Component_Country_Of_Origin: China; ShowFields: YES; ID: 2789
R56 = MCD-00521: Resistor, 75K, 0402, +/-1%, 1/16W; Part_Preference: Recommended; Manufacturer: YAGEO; Manufacturer_Part_Number: RC0402FR-0775KL; Component_Country_Of_Origin: China; ShowFields: YES; ID: 3220
R57 = MCD-00435: Resistor, 24K, 0402, +/-1%, 1/16W; Part_Preference: Recommended; Manufacturer: YAGEO; Manufacturer_Part_Number: RC0402FR-0724KL; Component_Country_Of_Origin: China; ShowFields: YES; ID: 2845
R69 = MCD-00052: Resistor, 0R, 0402, +/-5%, 1/16W; Manufacturer_Part_Number: RC0402JR-070RL; Manufacturer: YAGEO; Part_Preference: Recommended; Order_Code_RS: 9232516RL; Component_Country_Of_Origin: China; ShowFields: YES; ID: 2540
R210 = MCD-00441: Resistor, 270R, 0402, +/-1%, 1/16W; Manufacturer_Part_Number: RC0402FR-07270RL; Manufacturer: YAGEO; Part_Preference: Recommended; Component_Country_Of_Origin: China; ID: 2838; ShowFields: YES
U26 = MCD-04051: Power Management IC for STM32MP2x series with 3 step-down SMPS, 7 LDOs, 5 GPOs, VFQFPN40L (5.0 x 5.0 x 1.0 mm); Part_Preference: Recommended; Manufacturer: STMICROELECTRONICS; Component_Country_Of_Origin: Unknown; ShowFields: YES; ID: 6167
U54 = MCD-02243: Regulator, 3A, DC step-down switching; Manufacturer: STMICROELECTRONICS; Manufacturer_HQ_COO: EU; Part_Preference: Recommended; Part_Type: IC; Component_Country_Of_Origin: Malaysia; ID: 4343; Order_Code_RS: 168-7852; ShowFields: YES

## Sheet STM32MP23XXAK Power.SchDoc: Power MPU
size A3; Date: Not used; ApprovedBy: Not used; CheckedBy: Not used; Author: Not used; CompanyName: STMicroelectronics; DrawnBy: Not used; Engineer: Not used; Organization: Not used; Address1: Not used; Address2: Not used; Address3: Not used; Address4: Not used; DocumentNumber: Not used; Revision: Not used; SheetNumber: 5; SheetTotal: 7
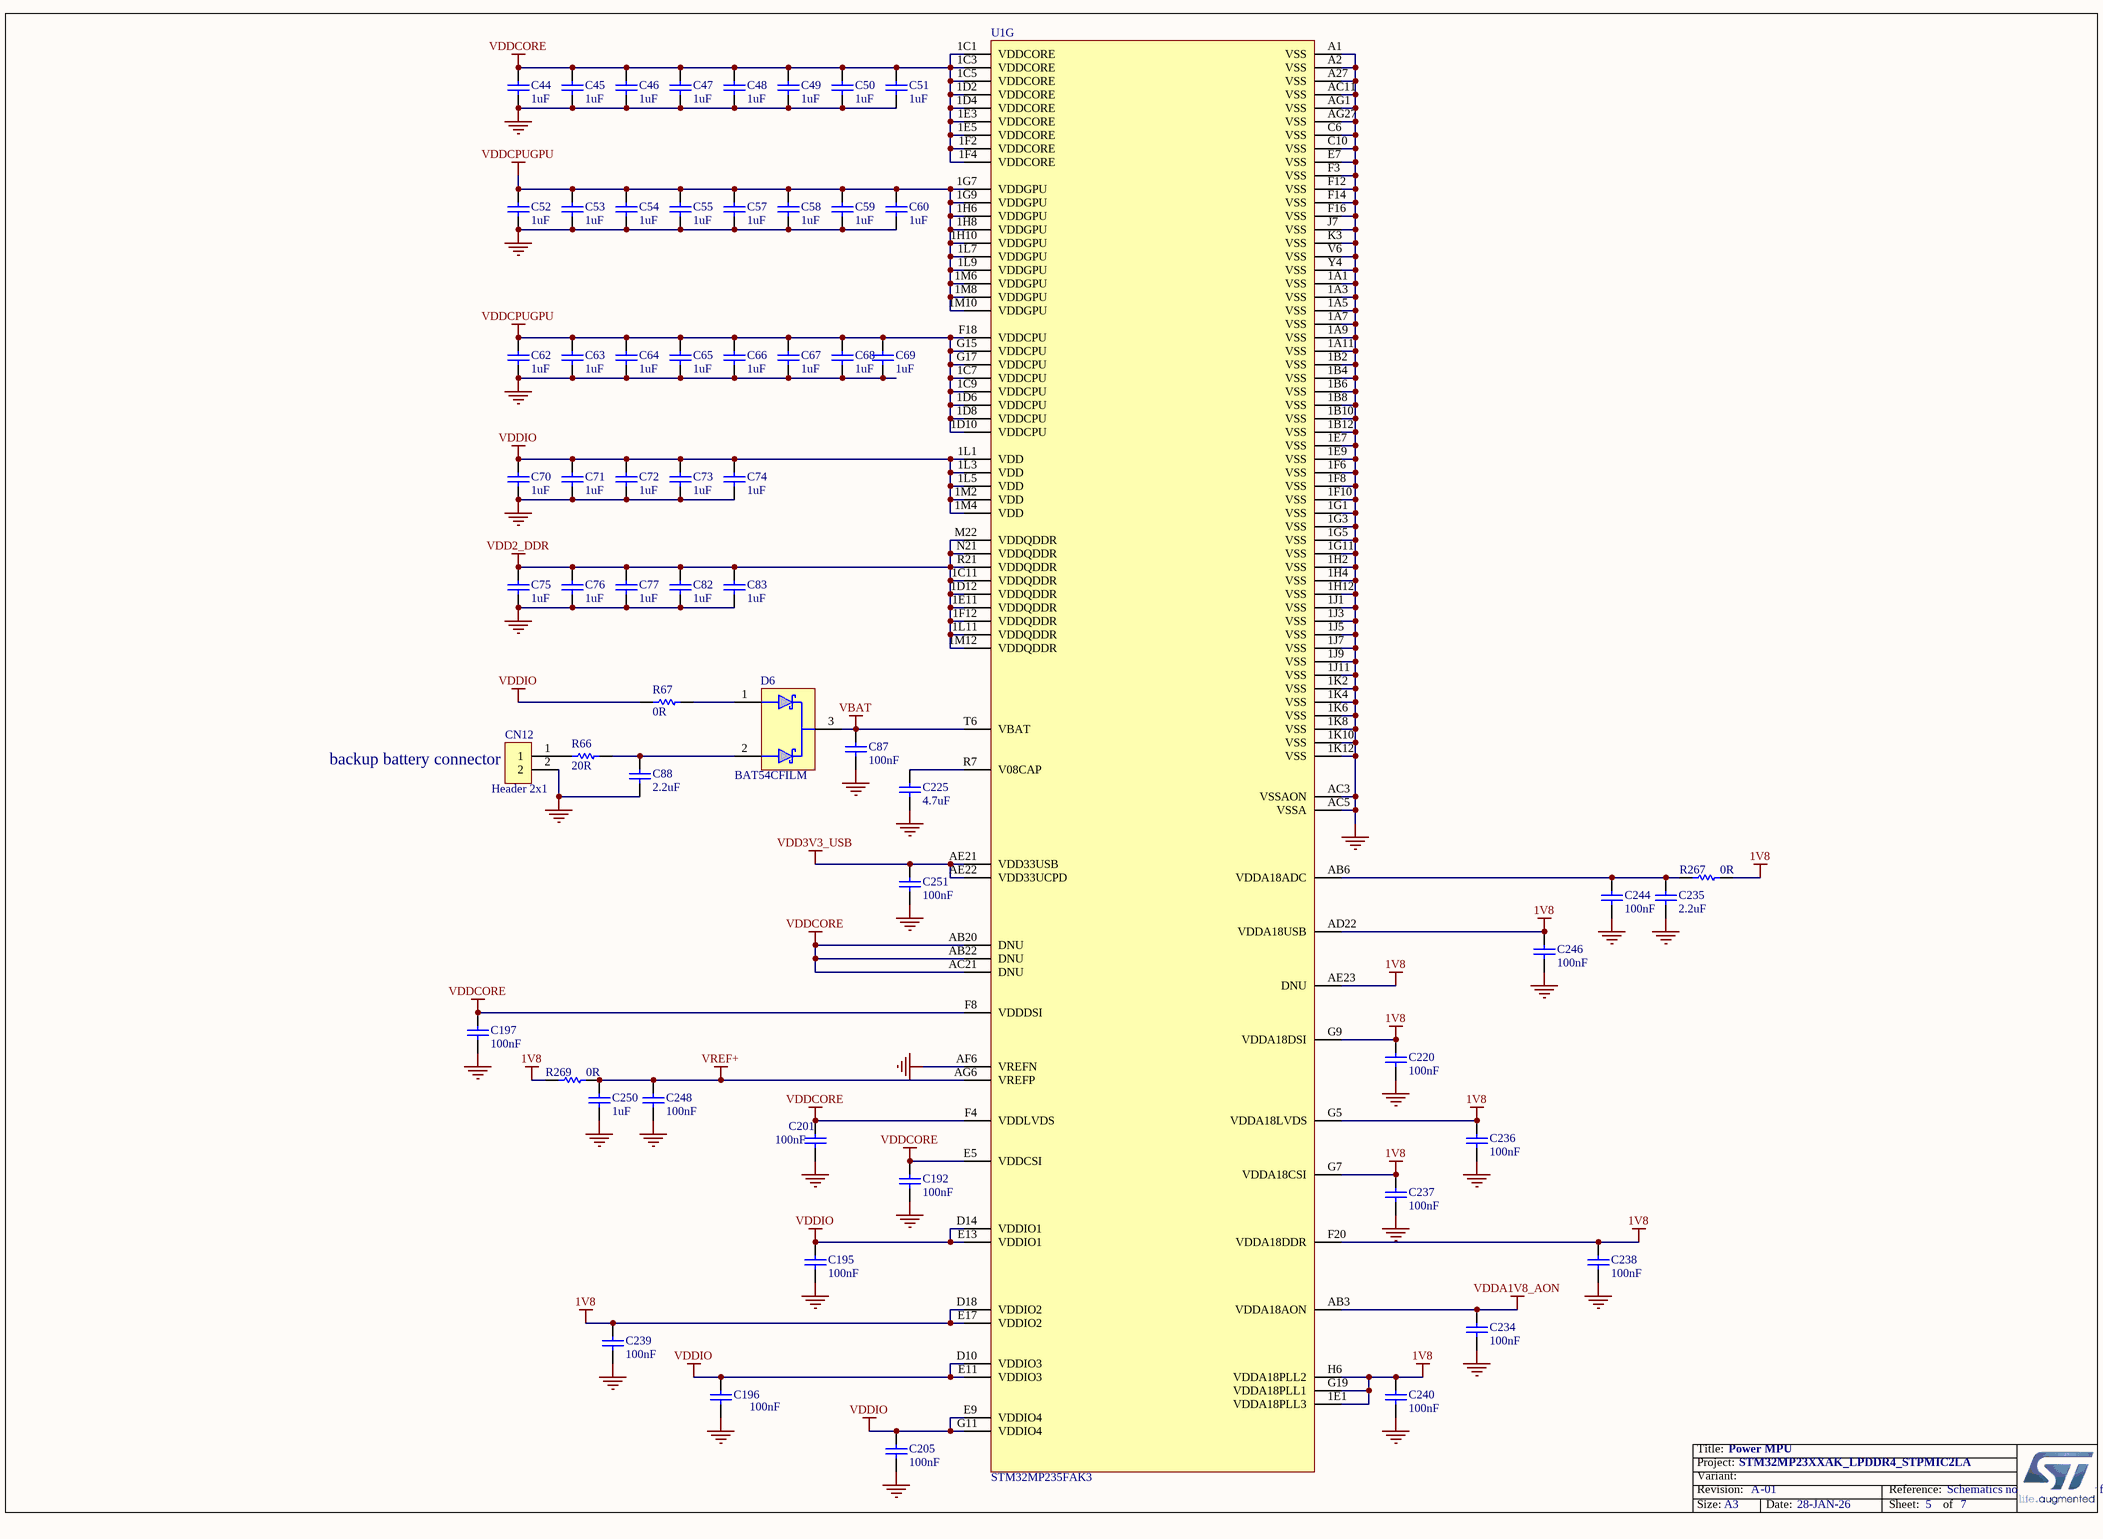
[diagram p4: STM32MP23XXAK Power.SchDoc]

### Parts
C44  1uF  [C0201_MURATA_GRM033_H0P3]
C45  1uF  [C0201_MURATA_GRM033_H0P3]
C46  1uF  [C0201_MURATA_GRM033_H0P3]
C47  1uF  [C0201_MURATA_GRM033_H0P3]
C48  1uF  [C0201_MURATA_GRM033_H0P3]
C49  1uF  [C0201_MURATA_GRM033_H0P3]
C50  1uF  [C0201_MURATA_GRM033_H0P3]
C51  1uF  [C0201_MURATA_GRM033_H0P3]
C52  1uF  [C0201_MURATA_GRM033_H0P3]
C53  1uF  [C0201_MURATA_GRM033_H0P3]
C54  1uF  [C0201_MURATA_GRM033_H0P3]
C55  1uF  [C0201_MURATA_GRM033_H0P3]
C57  1uF  [C0201_MURATA_GRM033_H0P3]
C58  1uF  [C0201_MURATA_GRM033_H0P3]
C59  1uF  [C0201_MURATA_GRM033_H0P3]
C60  1uF  [C0201_MURATA_GRM033_H0P3]
C62  1uF  [C0201_MURATA_GRM033_H0P3]
C63  1uF  [C0201_MURATA_GRM033_H0P3]
C64  1uF  [C0201_MURATA_GRM033_H0P3]
C65  1uF  [C0201_MURATA_GRM033_H0P3]
C66  1uF  [C0201_MURATA_GRM033_H0P3]
C67  1uF  [C0201_MURATA_GRM033_H0P3]
C68  1uF  [C0201_MURATA_GRM033_H0P3]
C69  1uF  [C0201_MURATA_GRM033_H0P3]
C70  1uF  [C0201_MURATA_GRM033_H0P3]
C71  1uF  [C0201_MURATA_GRM033_H0P3]
C72  1uF  [C0201_MURATA_GRM033_H0P3]
C73  1uF  [C0201_MURATA_GRM033_H0P3]
C74  1uF  [C0201_MURATA_GRM033_H0P3]
C75  1uF  [C0201_MURATA_GRM033_H0P3]
C76  1uF  [C0201_MURATA_GRM033_H0P3]
C77  1uF  [C0201_MURATA_GRM033_H0P3]
C82  1uF  [C0201_MURATA_GRM033_H0P3]
C83  1uF  [C0201_MURATA_GRM033_H0P3]
C87  value 100nF  [C0402]  (hidden comment: Capacitor)
C88  value 2.2uF  [C0402]  (hidden comment: Capacitor)
C192  value 100nF  [C0201_MURATA_GRM033_H0P3]  (hidden comment: Capacitor)
C195  value 100nF  [C0201_MURATA_GRM033_H0P3]  (hidden comment: Capacitor)
C196  value 100nF  [C0201_MURATA_GRM033_H0P3]  (hidden comment: Capacitor)
C197  value 100nF  [C0201_MURATA_GRM033_H0P3]  (hidden comment: Capacitor)
C201  value 100nF  [C0201_MURATA_GRM033_H0P3]  (hidden comment: Capacitor)
C205  value 100nF  [C0201_MURATA_GRM033_H0P3]  (hidden comment: Capacitor)
C220  value 100nF  [C0201_MURATA_GRM033_H0P3]  (hidden comment: Capacitor)
C225  value 4.7uF  [C0201_H0P5]  (hidden comment: Capacitor)
C234  value 100nF  [C0201_MURATA_GRM033_H0P3]  (hidden comment: Capacitor)
C235  value 2.2uF  [C0201_H0P5]  (hidden comment: Capacitor)
C236  value 100nF  [C0201_MURATA_GRM033_H0P3]  (hidden comment: Capacitor)
C237  value 100nF  [C0201_MURATA_GRM033_H0P3]  (hidden comment: Capacitor)
C238  value 100nF  [C0201_MURATA_GRM033_H0P3]  (hidden comment: Capacitor)
C239  value 100nF  [C0201_MURATA_GRM033_H0P3]  (hidden comment: Capacitor)
C240  value 100nF  [C0201_MURATA_GRM033_H0P3]  (hidden comment: Capacitor)
C244  value 100nF  [C0201_MURATA_GRM033_H0P3]  (hidden comment: Capacitor)
C246  value 100nF  [C0201_MURATA_GRM033_H0P3]  (hidden comment: Capacitor)
C248  value 100nF  [C0201_MURATA_GRM033_H0P3]  (hidden comment: Capacitor)
C250  value 1uF  [C0201_MURATA_GRM033_H0P3]  (hidden comment: Capacitor)
C251  value 100nF  [C0201_MURATA_GRM033_H0P3]  (hidden comment: Capacitor)
CN12  Header 2x1  [CON_MOLEX_53047-0210]
D6  value BAT54CFILM  [DIO_SOT23]  (hidden comment: DIODE_3P_DUAL_COMMON_CATHODE)
R66  value 20R  [R0402]  (hidden comment: Resistor)
R67  value 0R  [R0402]  (hidden comment: Resistor)
R267  value 0R  [R0402]  (hidden comment: Resistor)
R269  value 0R  [R0402]  (hidden comment: Resistor)
U1  value STM32MP235FAK3  [ICC_VFBGA424_14X14_P050_H1P0_CODE-B0MP]  (hidden comment: IC_STM32MP235FAK3)  (part G of 9)

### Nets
1V8: C220.2 C236.2 C237.2 C238.2 C239.2 C240.2 C246.2 R267.2 R269.1 U1.1E1(VDDA18PLL3) U1.AD22(VDDA18USB) U1.AE23(DNU) U1.D18(VDDIO2) U1.E17(VDDIO2) U1.F20(VDDA18DDR) U1.G5(VDDA18LVDS) U1.G7(VDDA18CSI) U1.G9(VDDA18DSI) U1.G19(VDDA18PLL1) U1.H6(VDDA18PLL2)
GND: C44.2 C45.1 C46.1 C47.2 C48.1 C49.1 C50.1 C51.1 C52.1 C53.1 C54.1 C55.1 C57.1 C58.1 C59.1 C60.1 C62.2 C63.1 C64.1 C65.2 C66.1 C67.1 C68.1 C69.1 C70.2 C71.1 C72.1 C73.2 C74.1 C75.1 C76.1 C77.2 C82.1 C83.1 C87.1 C88.1 C192.1 C195.1 C196.1 C197.1 C201.1 C205.1 C220.1 C225.1 C234.1 C235.1 C236.1 C237.1 C238.1 C239.1 C240.1 C244.1 C246.1 C248.1 C250.1 C251.1 CN12.2 U1.1A1(VSS) U1.1A3(VSS) U1.1A5(VSS) U1.1A7(VSS) U1.1A9(VSS) U1.1A11(VSS) U1.1B2(VSS) U1.1B4(VSS) U1.1B6(VSS) U1.1B8(VSS) U1.1B10(VSS) U1.1B12(VSS) U1.1E7(VSS) U1.1E9(VSS) U1.1F6(VSS) U1.1F8(VSS) U1.1F10(VSS) U1.1G1(VSS) U1.1G3(VSS) U1.1G5(VSS) U1.1G11(VSS) U1.1H2(VSS) U1.1H4(VSS) U1.1H12(VSS) U1.1J1(VSS) U1.1J3(VSS) U1.1J5(VSS) U1.1J7(VSS) U1.1J9(VSS) U1.1J11(VSS) U1.1K2(VSS) U1.1K4(VSS) U1.1K6(VSS) U1.1K8(VSS) U1.1K10(VSS) U1.1K12(VSS) U1.A1(VSS) U1.A2(VSS) U1.A27(VSS) U1.AC3(VSSAON) U1.AC5(VSSA) U1.AC11(VSS) U1.AF6(VREFN) U1.AG1(VSS) U1.AG27(VSS) U1.C6(VSS) U1.C10(VSS) U1.E7(VSS) U1.F3(VSS) U1.F12(VSS) U1.F14(VSS) U1.F16(VSS) U1.J7(VSS) U1.K3(VSS) U1.V6(VSS) U1.Y4(VSS)
VBAT: C87.2 D6.3 U1.T6(VBAT)
VDD2_DDR: C75.2 C76.2 C77.1 C82.2 C83.2 U1.1C11(VDDQDDR) U1.1D12(VDDQDDR) U1.1E11(VDDQDDR) U1.1F12(VDDQDDR) U1.1L11(VDDQDDR) U1.1M12(VDDQDDR) U1.M22(VDDQDDR) U1.N21(VDDQDDR) U1.R21(VDDQDDR)
VDD3V3_USB: C251.2 U1.AE21(VDD33USB) U1.AE22(VDD33UCPD)
VDDA1V8_AON: C234.2 U1.AB3(VDDA18AON)
VDDCORE: C44.1 C45.2 C46.2 C47.1 C48.2 C49.2 C50.2 C51.2 C192.2 C197.2 C201.2 U1.1C1(VDDCORE) U1.1C3(VDDCORE) U1.1C5(VDDCORE) U1.1D2(VDDCORE) U1.1D4(VDDCORE) U1.1E3(VDDCORE) U1.1E5(VDDCORE) U1.1F2(VDDCORE) U1.1F4(VDDCORE) U1.AB20(DNU) U1.AB22(DNU) U1.AC21(DNU) U1.E5(VDDCSI) U1.F4(VDDLVDS) U1.F8(VDDDSI)
VDDCPUGPU: C52.2 C53.2 C54.2 C55.2 C57.2 C58.2 C59.2 C60.2 C62.1 C63.2 C64.2 C65.1 C66.2 C67.2 C68.2 C69.2 U1.1C7(VDDCPU) U1.1C9(VDDCPU) U1.1D6(VDDCPU) U1.1D8(VDDCPU) U1.1D10(VDDCPU) U1.1G7(VDDGPU) U1.1G9(VDDGPU) U1.1H6(VDDGPU) U1.1H8(VDDGPU) U1.1H10(VDDGPU) U1.1L7(VDDGPU) U1.1L9(VDDGPU) U1.1M6(VDDGPU) U1.1M8(VDDGPU) U1.1M10(VDDGPU) U1.F18(VDDCPU) U1.G15(VDDCPU) U1.G17(VDDCPU)
VDDIO: C70.1 C71.2 C72.2 C73.1 C74.2 C195.2 C196.2 C205.2 R67.2 U1.1L1(VDD) U1.1L3(VDD) U1.1L5(VDD) U1.1M2(VDD) U1.1M4(VDD) U1.D10(VDDIO3) U1.D14(VDDIO1) U1.E9(VDDIO4) U1.E11(VDDIO3) U1.E13(VDDIO1) U1.G11(VDDIO4)
VREF+: C248.2 C250.2 R269.2 U1.AG6(VREFP)
NetC88_2: C88.2 D6.2 R66.2
NetC225_2: C225.2 U1.R7(V08CAP)
NetC235_2: C235.2 C244.2 R267.1 U1.AB6(VDDA18ADC)
NetCN12_1: CN12.1 R66.1
NetD6_1: D6.1 R67.1

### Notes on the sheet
- (near CN12) backup battery connector

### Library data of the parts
C44-C55 C57-C60 C62-C77 C82 C83 = MCD-02377: Capacitor, MLCC, 1uF, 6.3V, X5R, +/-20%, 0201, T=0,3mm; Part_Preference: Recommended; Manufacturer: MURATA; Manufacturer_Part_Number: GRM033R60J105MEA2; Partial_Alternate_Internal_Part_Number: MCD-04356; Order_Code_RS: 820-0643; Component_Country_Of_Origin: Japan°; ShowFields: YES; ID: 4483
C87 = MCD-00006: Capacitor, MLCC, 100nF, 16V, X7R, +/-10%, 0402, T=0.5mm; Manufacturer_Part_Number: CC0402KRX7R7BB104; Manufacturer: YAGEO; Part_Preference: Recommended; Partial_Alternate_Internal_Part_Number: MCD-03299; Order_Code_RS: 9402047; Component_Country_Of_Origin: China; ID: 2474; ShowFields: YES
C88 = MCD-01823: Capacitor, MLCC, 2.2uF, 6V3, X5R, +/-10%, 0402, T=0.5mm; Part_Preference: Recommended; Manufacturer: MURATA; Manufacturer_Part_Number: GRM155R60J225KE95; Partial_Alternate_Internal_Part_Number: MCD-03566; Order_Code_RS: 172-6478; Component_Country_Of_Origin: Japan°°; ID: 3923; ShowFields: YES; Alternate_EMS: A
C192 C195-C197 C201 C205 C220 C234 C236-C240 C244 C246 C248 C251 = MCD-01535: Capacitor, MLCC,100nF, 10V, C0G/NP0, +/-10%, 0201, T=0.3mm; Part_Preference: Recommended; Manufacturer: MURATA; Manufacturer_Part_Number: GRM033R61A104KE15; Order_Code_RS: 790-2742; Component_Country_Of_Origin: Japan°°; ID: 3635; ShowFields: YES
C225 = MCD-01534: Capacitor, MLCC, 4,7uF, 6V3, X5R, +/-20%, 0201, T=0.5mm; Part_Preference: Recommended; Manufacturer: MURATA; Manufacturer_Part_Number: GRM035R60J475ME15; Component_Country_Of_Origin: Japan°°; ID: 3634; ShowFields: YES
C235 = MCD-02235: Capacitor, MLCC, 2.2uF, 10V, X5R,+/-10%, 0201, T=0.5mm; Part_Preference: Recommended; Manufacturer: MURATA; Manufacturer_Part_Number: GRM033R61A225KE47; Order_Code_RS: NA; Component_Country_Of_Origin: Japan°°; ShowFields: YES; ID: 4335
C250 = MCD-02377: Capacitor, MLCC, 1uF, 6.3V, X5R, +/-20%, 0201, T=0,3mm; Manufacturer_Part_Number: GRM033R60J105MEA2; Manufacturer: MURATA; Part_Preference: Recommended; Partial_Alternate_Internal_Part_Number: MCD-04356; Order_Code_RS: 820-0643; Component_Country_Of_Origin: Japan°; ID: 4483; ShowFields: YES
CN12 = MCD-00655: Header, 2x1, 1.25mm, VR, TH, T=2.25mm/2.3mm; Part_Type: Connector; Manufacturer_Part_Number: 53047-0210; Manufacturer: MOLEX; BMS_Part_Number: 9083002; Part_Preference: Recommended; Partial_Alternate_Internal_Part_Number: MCD-04371, MCD-04208; Order_Code_RS: 279-9213; Component_Country_Of_Origin: Unknown; ID: 3091; ShowFields: YES
D6 = MCD-03280: Diode, Schottky, Dual Common Cathode, 0V3, 300mA, 40V, SOT-23; Part_Preference: Recommended; Manufacturer: STMICROELECTRONICS; Order_Code_RS: 795-8397; Component_Country_Of_Origin: China; ShowFields: YES; ID: 5396
R66 = MCD-00058: Resistor, 20R, 0402, +/-1%, 1/16W; BMS_Part_Number: 9131027; Part_Preference: Recommended; Manufacturer: YAGEO; Manufacturer_Part_Number: RC0402FR-0720RL; Order_Code_RS: 1799192; Component_Country_Of_Origin: China; ID: 2537; ShowFields: YES
R67 = MCD-00052: as R69 on sheet STPMIC2L
R267 R269 = MCD-00052: as R64 on sheet STM32MP23XXAK I_Os
U1 = MCD-05079: as U1 on sheet STM32MP23XXAK I_Os

## Sheet LPDDR4.SchDoc: LPDDR4
size A3; Date: Not used; ApprovedBy: Not used; CheckedBy: Not used; Author: Not used; CompanyName: STMicroelectronics; DrawnBy: Not used; Engineer: Not used; Organization: Not used; Address1: Not used; Address2: Not used; Address3: Not used; Address4: Not used; DocumentNumber: Not used; Revision: Not used; SheetNumber: 6; SheetTotal: 7
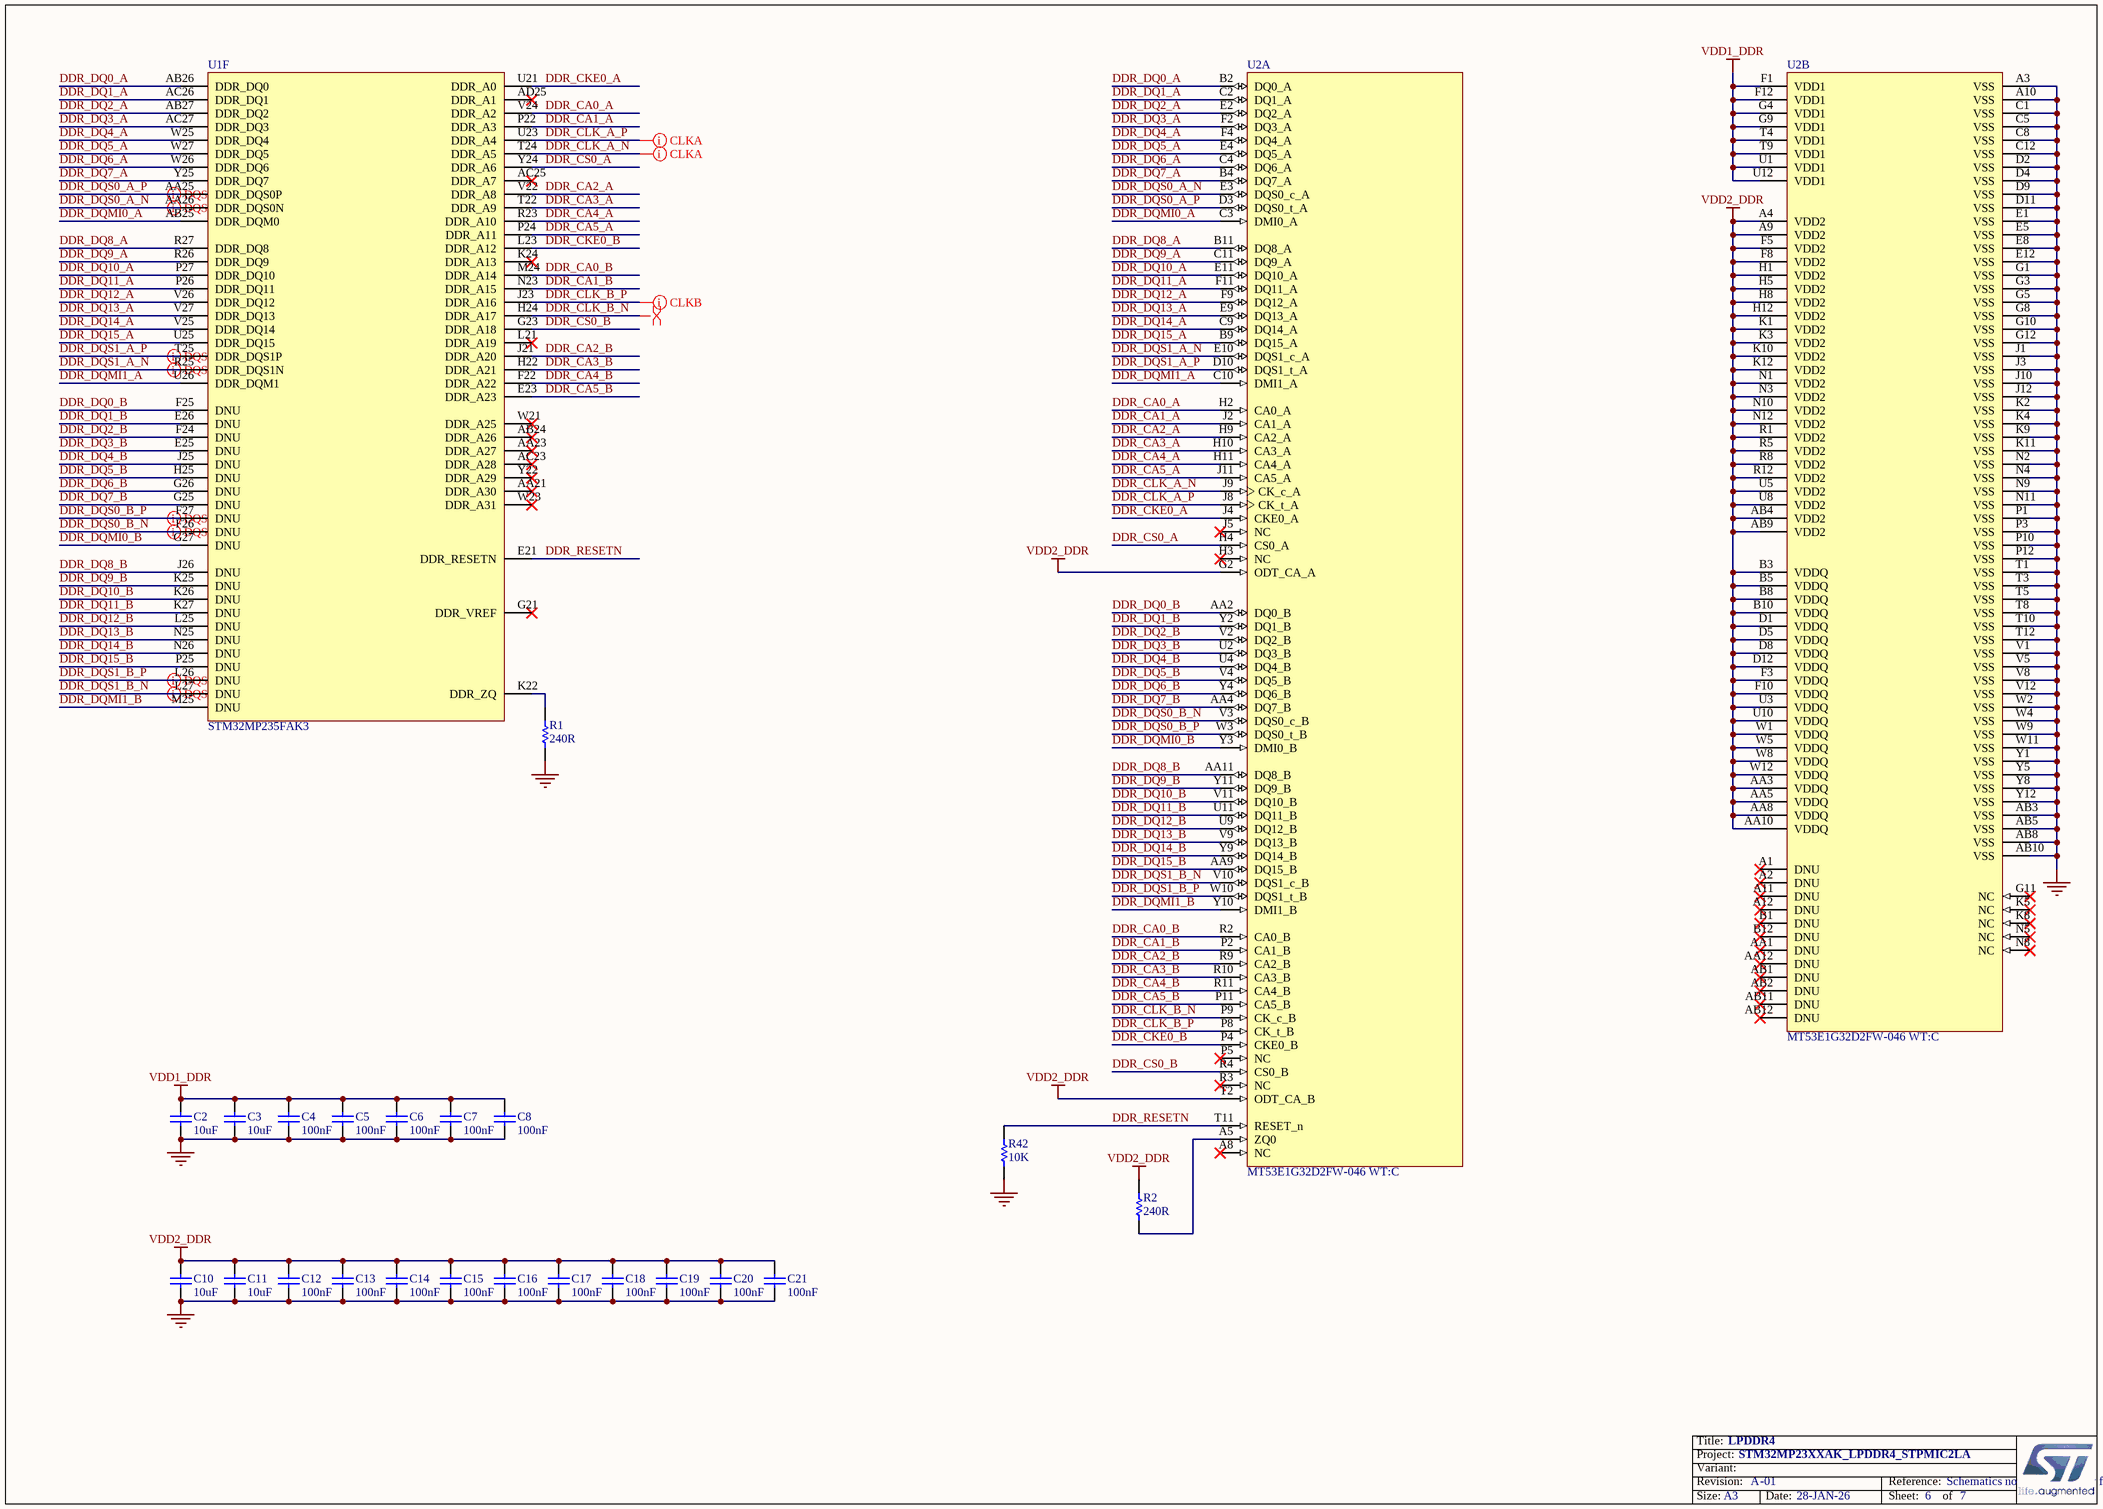
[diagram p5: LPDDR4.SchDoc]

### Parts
C2  value 10uF  [C0603]  (hidden comment: Capacitor)
C3  value 10uF  [C0603]  (hidden comment: Capacitor)
C4  100nF  [C0402]
C5  100nF  [C0402]
C6  100nF  [C0402]
C7  100nF  [C0402]
C8  100nF  [C0402]
C10  value 10uF  [C0603]  (hidden comment: Capacitor)
C11  value 10uF  [C0603]  (hidden comment: Capacitor)
C12  100nF  [C0402]
C13  100nF  [C0402]
C14  100nF  [C0402]
C15  100nF  [C0402]
C16  100nF  [C0402]
C17  100nF  [C0402]
C18  100nF  [C0402]
C19  100nF  [C0402]
C20  100nF  [C0402]
C21  100nF  [C0402]
R1  value 240R  [R0201_H0P23]  (hidden comment: Resistor)
R2  value 240R  [R0201_H0P23]  (hidden comment: Resistor)
R42  value 10K  [R0402]  (hidden comment: Resistor)
U1  value STM32MP235FAK3  [ICC_VFBGA424_14X14_P050_H1P0_CODE-B0MP]  (hidden comment: IC_STM32MP235FAK3)  (part F of 9)
U2  MT53E1G32D2FW-046 WT:C  [ICC_TFBGA200_10X14P5_P080_H1P05_PS0P3]  (parts A,B of 2)

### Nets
GND: C2.1 C3.1 C4.2 C5.2 C6.2 C7.2 C8.2 C10.1 C11.1 C12.2 C13.2 C14.2 C15.2 C16.2 C17.2 C18.2 C19.2 C20.2 C21.2 R1.1 R42.1 U2.A3(VSS) U2.A10(VSS) U2.AB3(VSS) U2.AB5(VSS) U2.AB8(VSS) U2.AB10(VSS) U2.C1(VSS) U2.C5(VSS) U2.C8(VSS) U2.C12(VSS) U2.D2(VSS) U2.D4(VSS) U2.D9(VSS) U2.D11(VSS) U2.E1(VSS) U2.E5(VSS) U2.E8(VSS) U2.E12(VSS) U2.G1(VSS) U2.G3(VSS) U2.G5(VSS) U2.G8(VSS) U2.G10(VSS) U2.G12(VSS) U2.J1(VSS) U2.J3(VSS) U2.J10(VSS) U2.J12(VSS) U2.K2(VSS) U2.K4(VSS) U2.K9(VSS) U2.K11(VSS) U2.N2(VSS) U2.N4(VSS) U2.N9(VSS) U2.N11(VSS) U2.P1(VSS) U2.P3(VSS) U2.P10(VSS) U2.P12(VSS) U2.T1(VSS) U2.T3(VSS) U2.T5(VSS) U2.T8(VSS) U2.T10(VSS) U2.T12(VSS) U2.V1(VSS) U2.V5(VSS) U2.V8(VSS) U2.V12(VSS) U2.W2(VSS) U2.W4(VSS) U2.W9(VSS) U2.W11(VSS) U2.Y1(VSS) U2.Y5(VSS) U2.Y8(VSS) U2.Y12(VSS)
VDD1_DDR: C2.2 C3.2 C4.1 C5.1 C6.1 C7.1 C8.1 U2.F1(VDD1) U2.F12(VDD1) U2.G4(VDD1) U2.G9(VDD1) U2.T4(VDD1) U2.T9(VDD1) U2.U1(VDD1) U2.U12(VDD1)
VDD2_DDR: C10.2 C11.2 C12.1 C13.1 C14.1 C15.1 C16.1 C17.1 C18.1 C19.1 C20.1 C21.1 R2.2 U2.A4(VDD2) U2.A9(VDD2) U2.AA3(VDDQ) U2.AA5(VDDQ) U2.AA8(VDDQ) U2.AA10(VDDQ) U2.AB4(VDD2) U2.AB9(VDD2) U2.B3(VDDQ) U2.B5(VDDQ) U2.B8(VDDQ) U2.B10(VDDQ) U2.D1(VDDQ) U2.D5(VDDQ) U2.D8(VDDQ) U2.D12(VDDQ) U2.F3(VDDQ) U2.F5(VDD2) U2.F8(VDD2) U2.F10(VDDQ) U2.G2(ODT_CA_A) U2.H1(VDD2) U2.H5(VDD2) U2.H8(VDD2) U2.H12(VDD2) U2.K1(VDD2) U2.K3(VDD2) U2.K10(VDD2) U2.K12(VDD2) U2.N1(VDD2) U2.N3(VDD2) U2.N10(VDD2) U2.N12(VDD2) U2.R1(VDD2) U2.R5(VDD2) U2.R8(VDD2) U2.R12(VDD2) U2.T2(ODT_CA_B) U2.U3(VDDQ) U2.U5(VDD2) U2.U8(VDD2) U2.U10(VDDQ) U2.W1(VDDQ) U2.W5(VDDQ) U2.W8(VDDQ) U2.W12(VDDQ)
DDR_CA0_A: U1.V24(DDR_A2) U2.H2(CA0_A)
DDR_CA0_B: U1.M24(DDR_A14) U2.R2(CA0_B)
DDR_CA1_A: U1.P22(DDR_A3) U2.J2(CA1_A)
DDR_CA1_B: U1.N23(DDR_A15) U2.P2(CA1_B)
DDR_CA2_A: U1.V22(DDR_A8) U2.H9(CA2_A)
DDR_CA2_B: U1.J21(DDR_A20) U2.R9(CA2_B)
DDR_CA3_A: U1.T22(DDR_A9) U2.H10(CA3_A)
DDR_CA3_B: U1.H22(DDR_A21) U2.R10(CA3_B)
DDR_CA4_A: U1.R23(DDR_A10) U2.H11(CA4_A)
DDR_CA4_B: U1.F22(DDR_A22) U2.R11(CA4_B)
DDR_CA5_A: U1.P24(DDR_A11) U2.J11(CA5_A)
DDR_CA5_B: U1.E23(DDR_A23) U2.P11(CA5_B)
DDR_CKE0_A: U1.U21(DDR_A0) U2.J4(CKE0_A)
DDR_CKE0_B: U1.L23(DDR_A12) U2.P4(CKE0_B)
DDR_CLK_A_N: U1.T24(DDR_A5) U2.J9(CK_c_A)
DDR_CLK_A_P: U1.U23(DDR_A4) U2.J8(CK_t_A)
DDR_CLK_B_N: U1.H24(DDR_A17) U2.P9(CK_c_B)
DDR_CLK_B_P: U1.J23(DDR_A16) U2.P8(CK_t_B)
DDR_CS0_A: U1.Y24(DDR_A6) U2.H4(CS0_A)
DDR_CS0_B: U1.G23(DDR_A18) U2.R4(CS0_B)
DDR_DQ0_A: U1.AB26(DDR_DQ0) U2.B2(DQ0_A)
DDR_DQ0_B: U1.F25(DNU) U2.AA2(DQ0_B)
DDR_DQ1_A: U1.AC26(DDR_DQ1) U2.C2(DQ1_A)
DDR_DQ1_B: U1.E26(DNU) U2.Y2(DQ1_B)
DDR_DQ2_A: U1.AB27(DDR_DQ2) U2.E2(DQ2_A)
DDR_DQ2_B: U1.F24(DNU) U2.V2(DQ2_B)
DDR_DQ3_A: U1.AC27(DDR_DQ3) U2.F2(DQ3_A)
DDR_DQ3_B: U1.E25(DNU) U2.U2(DQ3_B)
DDR_DQ4_A: U1.W25(DDR_DQ4) U2.F4(DQ4_A)
DDR_DQ4_B: U1.J25(DNU) U2.U4(DQ4_B)
DDR_DQ5_A: U1.W27(DDR_DQ5) U2.E4(DQ5_A)
DDR_DQ5_B: U1.H25(DNU) U2.V4(DQ5_B)
DDR_DQ6_A: U1.W26(DDR_DQ6) U2.C4(DQ6_A)
DDR_DQ6_B: U1.G26(DNU) U2.Y4(DQ6_B)
DDR_DQ7_A: U1.Y25(DDR_DQ7) U2.B4(DQ7_A)
DDR_DQ7_B: U1.G25(DNU) U2.AA4(DQ7_B)
DDR_DQ8_A: U1.R27(DDR_DQ8) U2.B11(DQ8_A)
DDR_DQ8_B: U1.J26(DNU) U2.AA11(DQ8_B)
DDR_DQ9_A: U1.R26(DDR_DQ9) U2.C11(DQ9_A)
DDR_DQ9_B: U1.K25(DNU) U2.Y11(DQ9_B)
DDR_DQ10_A: U1.P27(DDR_DQ10) U2.E11(DQ10_A)
DDR_DQ10_B: U1.K26(DNU) U2.V11(DQ10_B)
DDR_DQ11_A: U1.P26(DDR_DQ11) U2.F11(DQ11_A)
DDR_DQ11_B: U1.K27(DNU) U2.U11(DQ11_B)
DDR_DQ12_A: U1.V26(DDR_DQ12) U2.F9(DQ12_A)
DDR_DQ12_B: U1.L25(DNU) U2.U9(DQ12_B)
DDR_DQ13_A: U1.V27(DDR_DQ13) U2.E9(DQ13_A)
DDR_DQ13_B: U1.N25(DNU) U2.V9(DQ13_B)
DDR_DQ14_A: U1.V25(DDR_DQ14) U2.C9(DQ14_A)
DDR_DQ14_B: U1.N26(DNU) U2.Y9(DQ14_B)
DDR_DQ15_A: U1.U25(DDR_DQ15) U2.B9(DQ15_A)
DDR_DQ15_B: U1.P25(DNU) U2.AA9(DQ15_B)
DDR_DQMI0_A: U1.AB25(DDR_DQM0) U2.C3(DMI0_A)
DDR_DQMI0_B: U1.G27(DNU) U2.Y3(DMI0_B)
DDR_DQMI1_A: U1.U26(DDR_DQM1) U2.C10(DMI1_A)
DDR_DQMI1_B: U1.M25(DNU) U2.Y10(DMI1_B)
DDR_DQS0_A_N: U1.AA26(DDR_DQS0N) U2.E3(DQS0_c_A)
DDR_DQS0_A_P: U1.AA25(DDR_DQS0P) U2.D3(DQS0_t_A)
DDR_DQS0_B_N: U1.F26(DNU) U2.V3(DQS0_c_B)
DDR_DQS0_B_P: U1.F27(DNU) U2.W3(DQS0_t_B)
DDR_DQS1_A_N: U1.R25(DDR_DQS1N) U2.E10(DQS1_c_A)
DDR_DQS1_A_P: U1.T25(DDR_DQS1P) U2.D10(DQS1_t_A)
DDR_DQS1_B_N: U1.L27(DNU) U2.V10(DQS1_c_B)
DDR_DQS1_B_P: U1.L26(DNU) U2.W10(DQS1_t_B)
DDR_RESETN: R42.2 U1.E21(DDR_RESETN) U2.T11(RESET_n)
NetR1_2: R1.2 U1.K22(DDR_ZQ)
NetR2_1: R2.1 U2.A5(ZQ0)

Not connected (* = marked no-connect by the designer): U1 AA21(DDR_A30)* AA23(DDR_A27)* AB24(DDR_A26)* AC23(DDR_A28)* AC25(DDR_A7)* AD25(DDR_A1)* G21(DDR_VREF)* K24(DDR_A13)* L21(DDR_A19)* W21(DDR_A25)* W23(DDR_A31)* Y22(DDR_A29)*; U2 A1(DNU)* A2(DNU)* A8(NC)* A11(DNU)* A12(DNU)* AA1(DNU)* AA12(DNU)* AB1(DNU)* AB2(DNU)* AB11(DNU)* AB12(DNU)* B1(DNU)* B12(DNU)* G11(NC)* H3(NC)* J5(NC)* K5(NC)* K8(NC)* N5(NC)* N8(NC)* P5(NC)* R3(NC)*

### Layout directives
differential pair: DDR_CLK_A_N, DDR_CLK_A_P, DDR_CLK_B_N, DDR_CLK_B_P, DDR_DQS0_A_N, DDR_DQS0_A_P, DDR_DQS0_B_N, DDR_DQS0_B_P, DDR_DQS1_A_N, DDR_DQS1_A_P, DDR_DQS1_B_N, DDR_DQS1_B_P

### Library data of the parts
C2 C3 C10 C11 = MCD-01341: Capacitor, MLCC, 10uF, 6V3, X5R, 20%, 0603, T=0.8mm; Manufacturer_Part_Number: GRM188R60J106ME47; Manufacturer: MURATA; Part_Preference: Recommended; Partial_Alternate_Internal_Part_Number: MCD-04454; Component_Country_Of_Origin: Japan°°; ID: 3441; ShowFields: YES
C4-C8 C12-C21 = MCD-00006: Capacitor, MLCC, 100nF, 16V, X7R, +/-10%, 0402, T=0.5mm; Part_Preference: Recommended; Manufacturer: YAGEO; Manufacturer_Part_Number: CC0402KRX7R7BB104; Partial_Alternate_Internal_Part_Number: MCD-03299; Order_Code_RS: 9402047; Component_Country_Of_Origin: China; ShowFields: YES; ID: 2474
R1 R2 = MCD-02253: Resistor, 240R, 0201, +/-1%, 1/20W; Part_Preference: Recommended; Manufacturer: YAGEO; Manufacturer_Part_Number: RC0201FR-07240RL; Component_Country_Of_Origin: China; ID: 4353; ShowFields: YES
R42 = MCD-00053: as R272 on sheet STM32MP23XXAK I_Os
U1 = MCD-05079: as U1 on sheet STM32MP23XXAK I_Os
U2 = MCD-04160: Memory, LPDDR4 SDRAM,1V8, 32Gbit, 2133MHz; Part_Type: IC; Part_Preference: Recommended; Manufacturer: MICRON; ShowFields: YES; ID: 6276; Component_Country_Of_Origin: Taiwan

## Sheet eMMC.SchDoc: eMMC
size A3; Date: Not used; ApprovedBy: Not used; CheckedBy: Not used; Author: Not used; CompanyName: STMicroelectronics; DrawnBy: Not used; Engineer: Not used; Organization: Not used; Address1: Not used; Address2: Not used; Address3: Not used; Address4: Not used; DocumentNumber: Not used; Revision: Not used; SheetNumber: 7; SheetTotal: 7
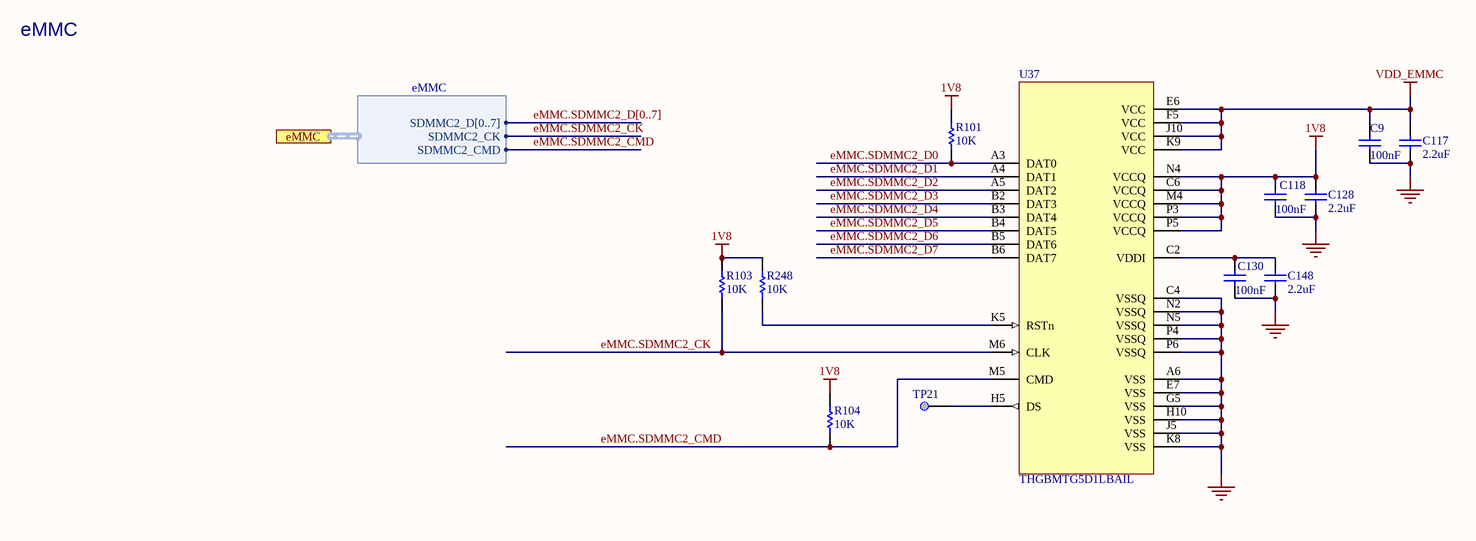
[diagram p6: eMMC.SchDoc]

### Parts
C9  value 100nF  [C0402]  (hidden comment: Capacitor)
C117  value 2.2uF  [C0402]  (hidden comment: Capacitor)
C118  value 100nF  [C0402]  (hidden comment: Capacitor)
C128  value 2.2uF  [C0402]  (hidden comment: Capacitor)
C130  value 100nF  [C0402]  (hidden comment: Capacitor)
C148  value 2.2uF  [C0402]  (hidden comment: Capacitor)
R101  value 10K  [R0402]  (hidden comment: Resistor)
R103  value 10K  [R0402]  (hidden comment: Resistor)
R104  value 10K  [R0402]  (hidden comment: Resistor)
R248  value 10K  [R0402]  (hidden comment: Resistor)
TP21  Test Point  [TP_SMD_1MM]  (value not drawn)  (no BOM)
U37  value THGBMTG5D1LBAIL  [ICC_P-WFBGA153_13X11P5_P050]  (hidden comment: eMMC_THGBMTG5D1LBAIL)

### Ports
eMMC (harness eMMC)

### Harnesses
eMMC: SDMMC2_CK, SDMMC2_CMD, SDMMC2_D[0..7]

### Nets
1V8: C118.2 C128.2 R101.2 R103.2 R104.2 R248.2 U37.C6(VCCQ) U37.M4(VCCQ) U37.N4(VCCQ) U37.P3(VCCQ) U37.P5(VCCQ)
GND: C9.1 C117.1 C118.1 C128.1 C130.1 C148.1 U37.A6(VSS) U37.C4(VSSQ) U37.E7(VSS) U37.G5(VSS) U37.H10(VSS) U37.J5(VSS) U37.K8(VSS) U37.N2(VSSQ) U37.N5(VSSQ) U37.P4(VSSQ) U37.P6(VSSQ)
VDD_EMMC: C9.2 C117.2 U37.E6(VCC) U37.F5(VCC) U37.J10(VCC) U37.K9(VCC)
eMMC.SDMMC2_CK: R103.1 U37.M6(CLK) ; port eMMC.SDMMC2_CK
eMMC.SDMMC2_CMD: R104.1 U37.M5(CMD) ; port eMMC.SDMMC2_CMD
eMMC.SDMMC2_D0: R101.1 U37.A3(DAT0)
eMMC.SDMMC2_D1: U37.A4(DAT1)
eMMC.SDMMC2_D2: U37.A5(DAT2)
eMMC.SDMMC2_D3: U37.B2(DAT3)
eMMC.SDMMC2_D4: U37.B3(DAT4)
eMMC.SDMMC2_D5: U37.B4(DAT5)
eMMC.SDMMC2_D6: U37.B5(DAT6)
eMMC.SDMMC2_D7: U37.B6(DAT7)
NetC130_2: C130.2 C148.2 U37.C2(VDDI)
NetR248_1: R248.1 U37.K5(RSTn)
NetTP21_1: TP21.1 U37.H5(DS)

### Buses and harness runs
bus eMMC.SDMMC2_D[0..7]

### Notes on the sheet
- eMMC

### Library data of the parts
C9 C118 C130 = MCD-00006: Capacitor, MLCC, 100nF, 16V, X7R, +/-10%, 0402, T=0.5mm; Part_Preference: Recommended; Manufacturer: YAGEO; Manufacturer_Part_Number: CC0402KRX7R7BB104; Partial_Alternate_Internal_Part_Number: MCD-03299; Order_Code_RS: 9402047; Component_Country_Of_Origin: China; ID: 2474; ShowFields: YES
C117 C128 C148 = MCD-02606: Capacitor, MLCC, 2.2uF, 6.3V, X5R, +/-10%, 0402, T=0.5mm; Part_Preference: Recommended; Manufacturer: YAGEO; Manufacturer_Part_Number: CC0402KRX5R5BB225; Order_Code_RS: 1992205; ShowFields: YES; ID: 4712; Component_Country_Of_Origin: China°
R101 R103 R104 R248 = MCD-00053: Resistor, 10K, 0402, +/-1%, 1/16W; Manufacturer_Part_Number: RC0402FR-0710KL; Manufacturer: YAGEO; BMS_Part_Number: 9131590; Part_Preference: Recommended; Order_Code_RS: 9239359; Component_Country_Of_Origin: China; ID: 2539; ShowFields: YES
TP21 = MCD-00074: Test Point, SMD, 1mm; Part_Type: Misc; Part_Preference: Recommended; Component_Country_Of_Origin: Unknown; ID: 2518; ShowFields: YES
U37 = MCD-02799: Memory, eMMC, 3V3, 4Gbit, 52MHz; Part_Type: IC; Part_Preference: Not recommended; Manufacturer: KIOXIA; ShowFields: YES; ID: 4911; Component_Country_Of_Origin: Unknown

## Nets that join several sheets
1V8: STPMIC2L (C193.1 U26.37), STM32MP23XXAK Power (20 pins), eMMC (11 pins)
GND: STM32MP23XXAK I_Os (7 pins), STPMIC2L (45 pins), STM32MP23XXAK Power (113 pins), LPDDR4 (79 pins), eMMC (17 pins)
VDD1_DDR: STPMIC2L (C40.1 U26.2), LPDDR4 (15 pins)
VDD2_DDR: STPMIC2L (5 pins), STM32MP23XXAK Power (14 pins), LPDDR4 (59 pins)
VDD3V3_USB: STPMIC2L (C61.1 U26.38), STM32MP23XXAK Power (C251.2 U1.AE21 U1.AE22)
VDD_EMMC: STPMIC2L (C190.1 U26.32), eMMC (6 pins)
VDDA1V8_AON: STM32MP23XXAK I_Os (U1.W2), STPMIC2L (C189.1 U26.1), STM32MP23XXAK Power (C234.2 U1.AB3)
VDDCORE: STPMIC2L (6 pins), STM32MP23XXAK Power (26 pins)
VDDCPUGPU: STPMIC2L (6 pins), STM32MP23XXAK Power (34 pins)
VDDIO: STM32MP23XXAK I_Os (R260.2 R261.2), STPMIC2L (C185.1 U26.31 U26.33), STM32MP23XXAK Power (20 pins)
eMMC.SDMMC2_CK: STM32MP23XXAK I_Os (U1.B25), eMMC (R103.1 U37.M6)
eMMC.SDMMC2_CMD: STM32MP23XXAK I_Os (U1.D24), eMMC (R104.1 U37.M5)
eMMC.SDMMC2_D0: STM32MP23XXAK I_Os (U1.C24), eMMC (R101.1 U37.A3)
eMMC.SDMMC2_D1: STM32MP23XXAK I_Os (U1.B23), eMMC (U37.A4)
eMMC.SDMMC2_D2: STM32MP23XXAK I_Os (U1.C23), eMMC (U37.A5)
eMMC.SDMMC2_D3: STM32MP23XXAK I_Os (U1.C25), eMMC (U37.B2)
eMMC.SDMMC2_D4: STM32MP23XXAK I_Os (U1.D22), eMMC (U37.B3)
eMMC.SDMMC2_D5: STM32MP23XXAK I_Os (U1.A23), eMMC (U37.B4)
eMMC.SDMMC2_D6: STM32MP23XXAK I_Os (U1.A22), eMMC (U37.B5)
eMMC.SDMMC2_D7: STM32MP23XXAK I_Os (U1.B22), eMMC (U37.B6)
I2C7.SCL: STM32MP23XXAK I_Os (R261.1 U1.E15), STPMIC2L (U26.20)
I2C7.SDA: STM32MP23XXAK I_Os (R260.1 U1.E19), STPMIC2L (U26.19)
NRST: STM32MP23XXAK I_Os (C33.2 U1.AE1), STPMIC2L (U26.21)
NRSTC1MS: STM32MP23XXAK I_Os (R272.1 U1.W3), STPMIC2L (U26.10)
PA0_WKUP: STM32MP23XXAK I_Os (U1.AF5), STPMIC2L (U26.22)
PWR_CPU_ON: STM32MP23XXAK I_Os (R272.2 U1.AB4), STPMIC2L (U26.9)
PWR_ON: STM32MP23XXAK I_Os (U1.AD3), STPMIC2L (U26.8)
